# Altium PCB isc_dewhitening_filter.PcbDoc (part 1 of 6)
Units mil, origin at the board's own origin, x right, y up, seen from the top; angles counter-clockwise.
Board outline 8440 x 7000 mil, 6 copper layers (Top Layer, MidLayer1, InternalPlane1, Internal Plane 3, InternalPlane2, Bottom Layer); 550 components, 462 nets, 2189 pads, 795 vias.
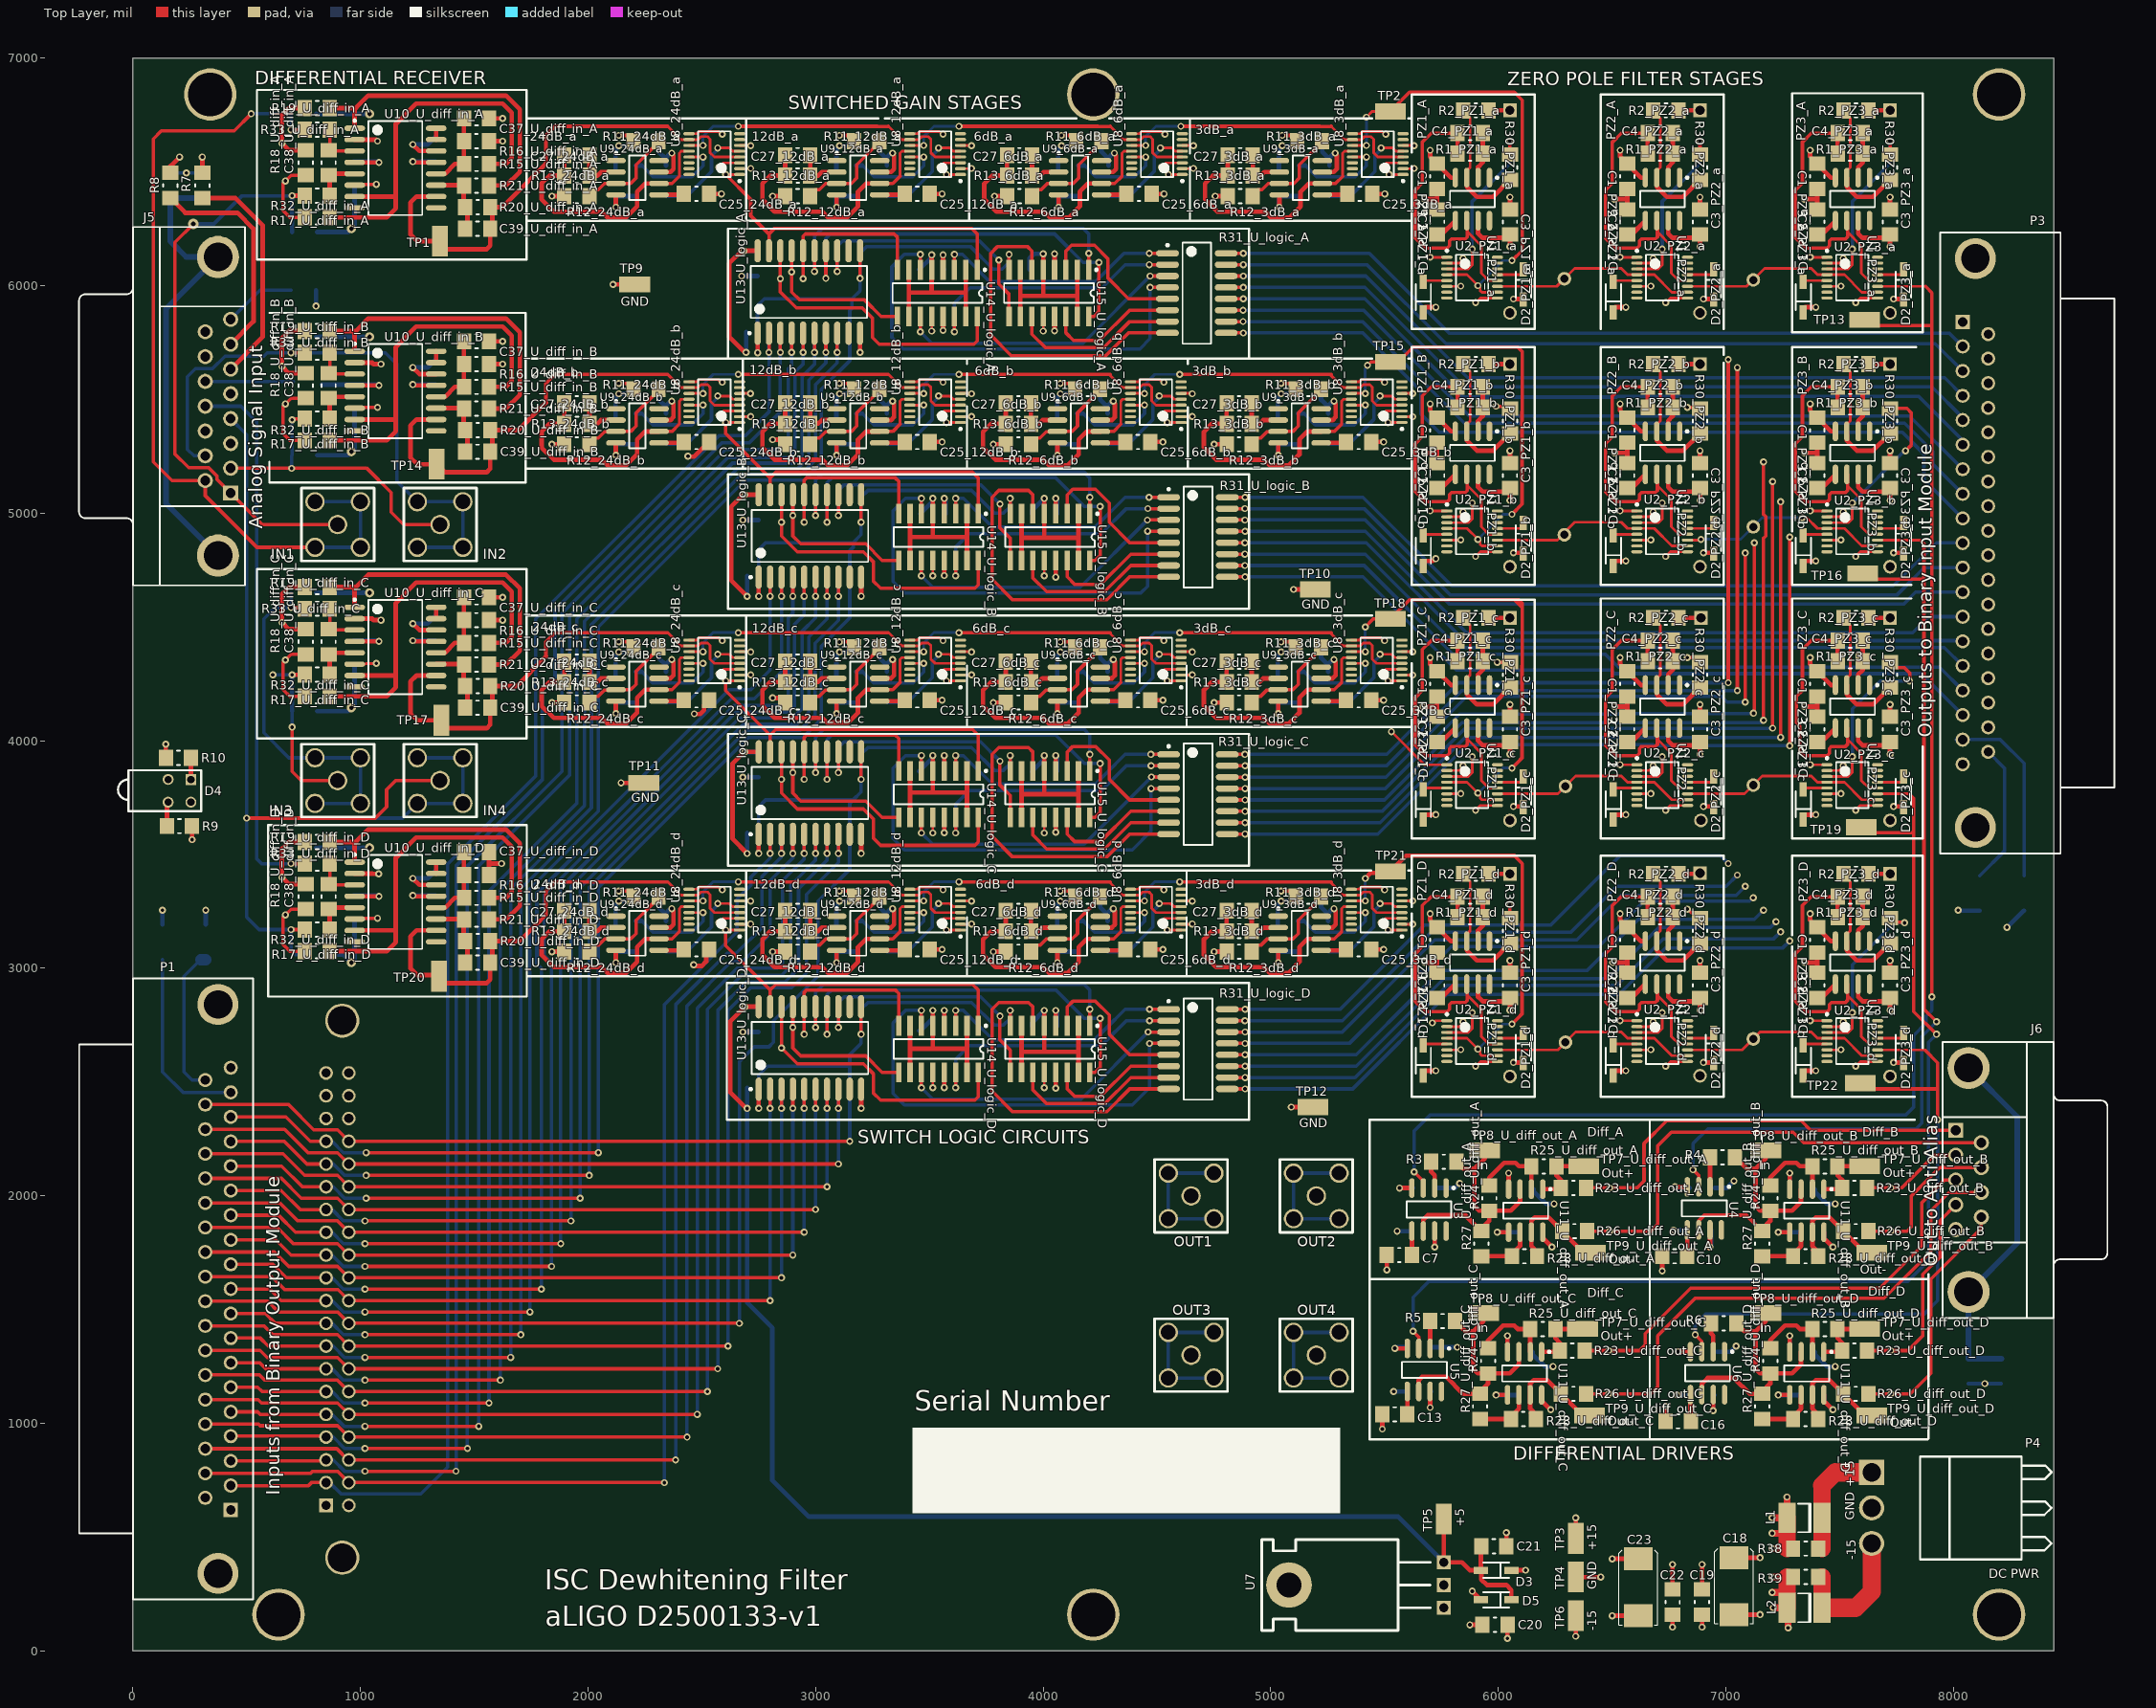
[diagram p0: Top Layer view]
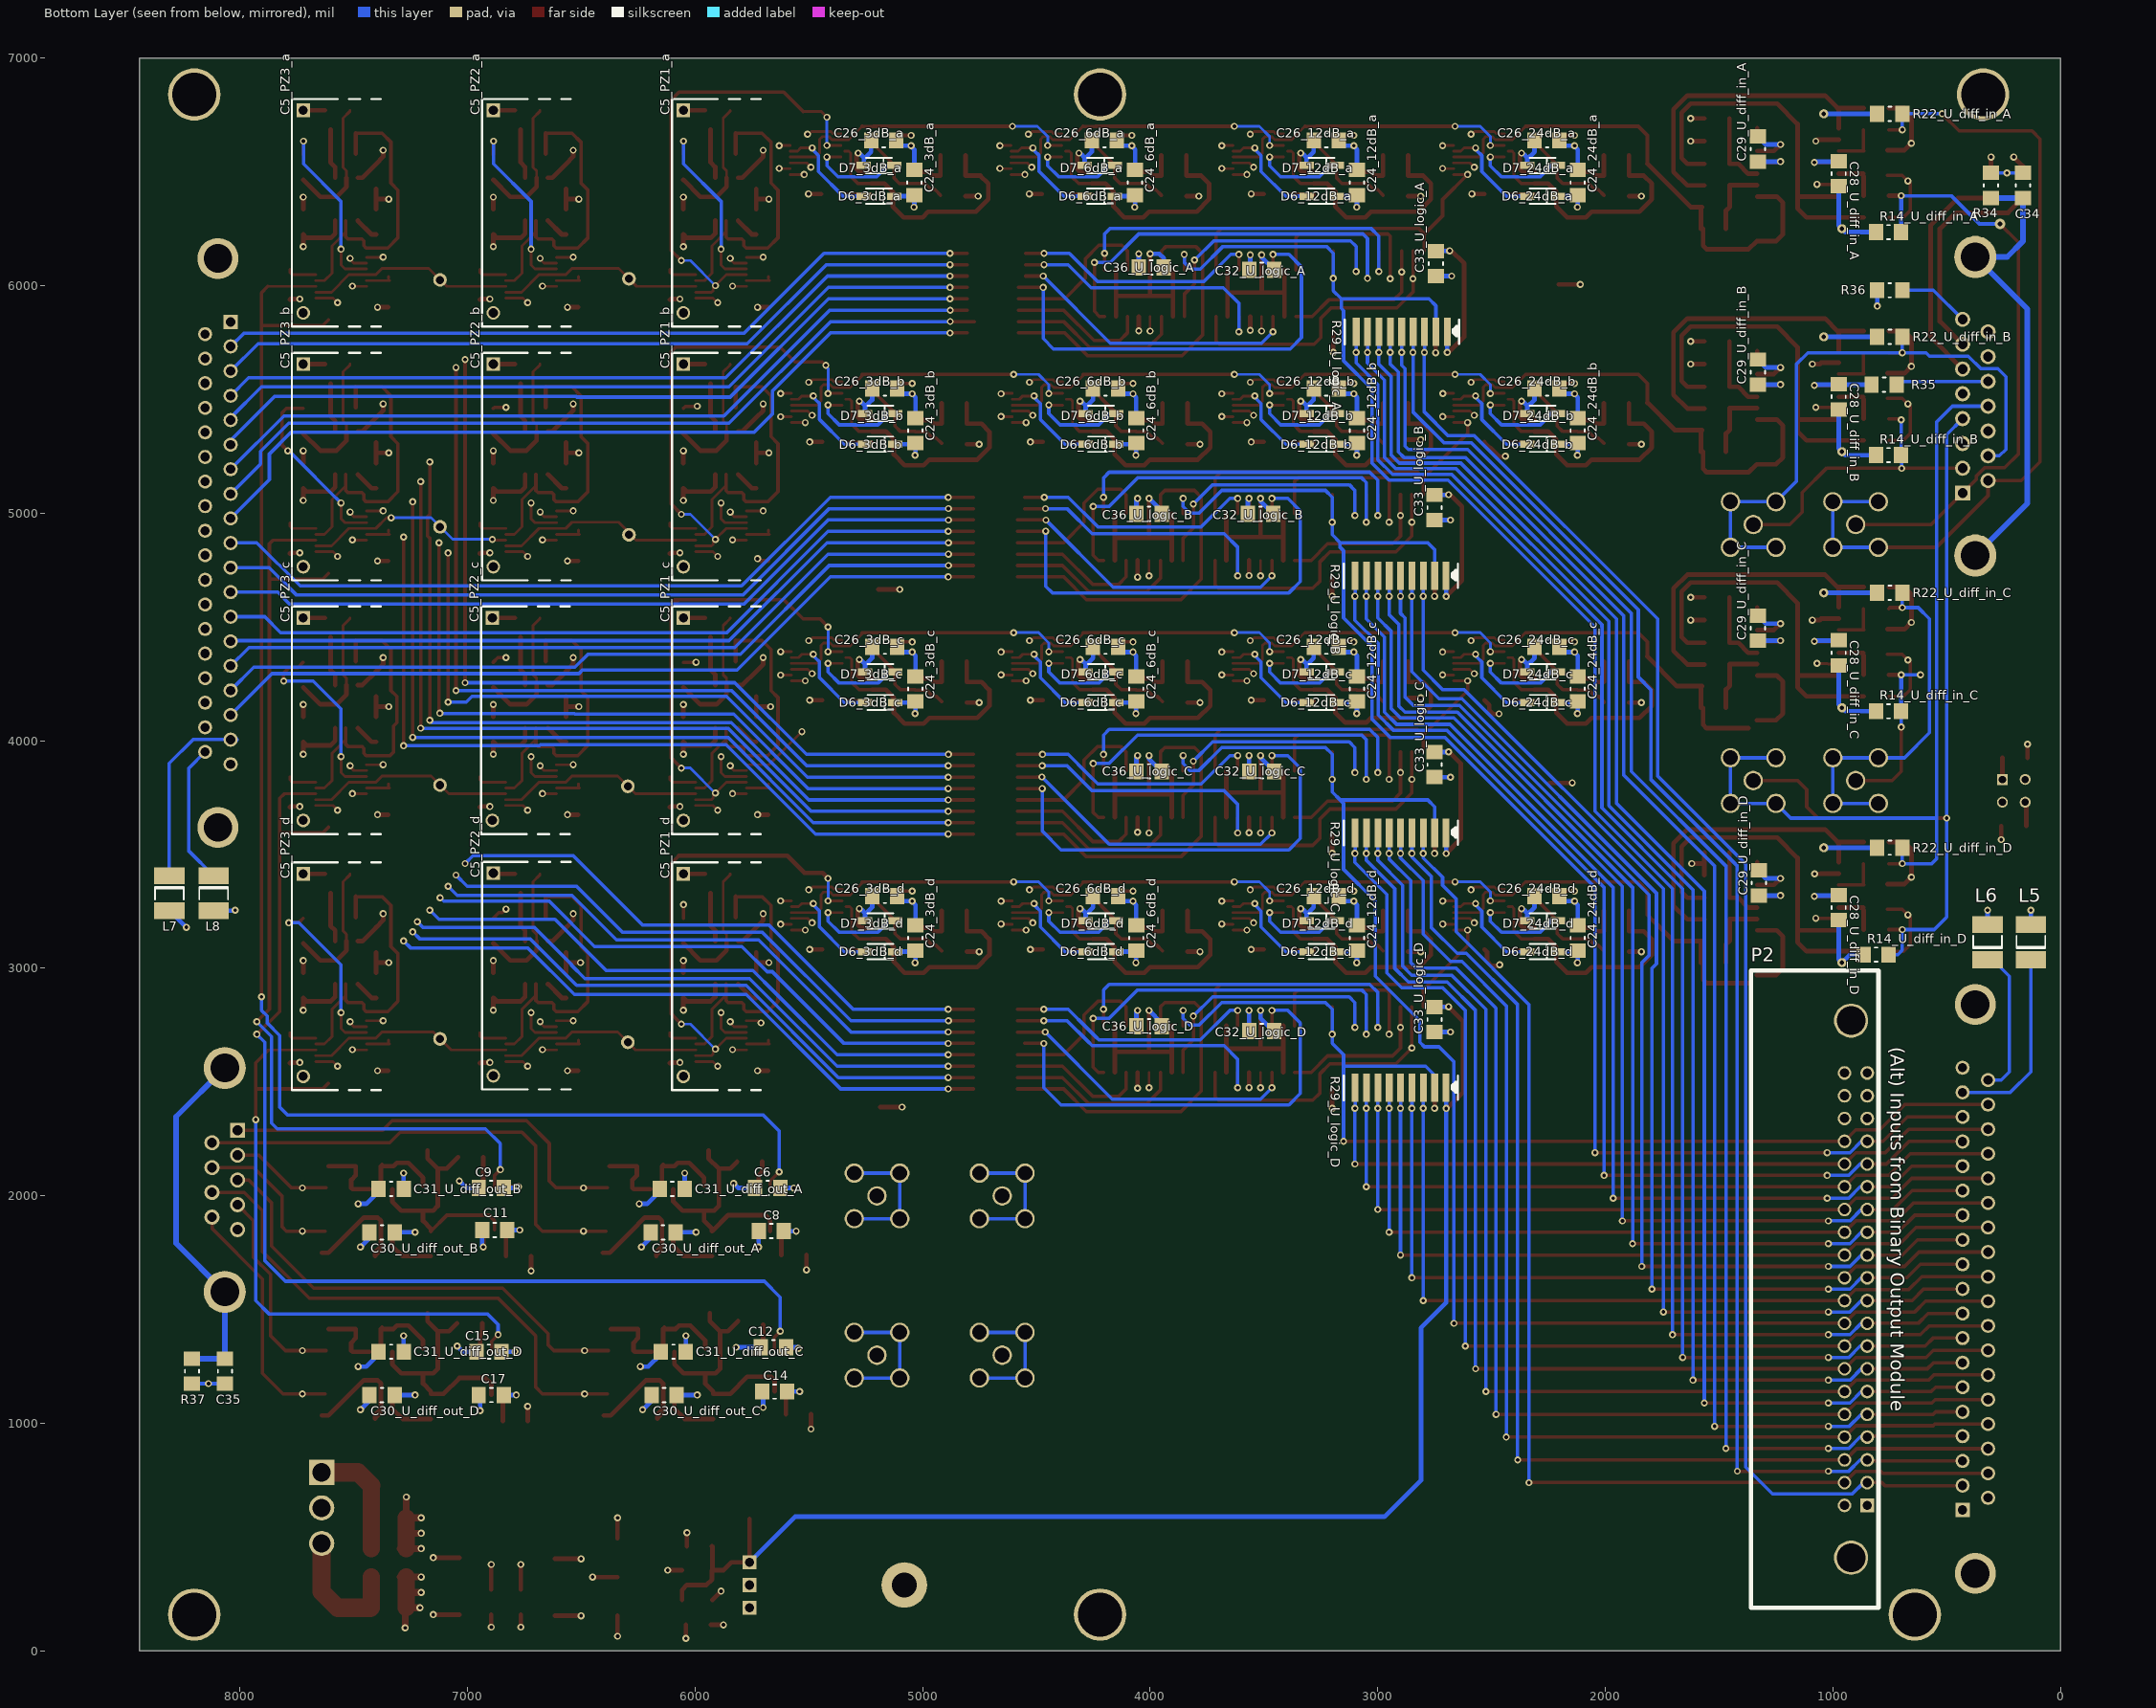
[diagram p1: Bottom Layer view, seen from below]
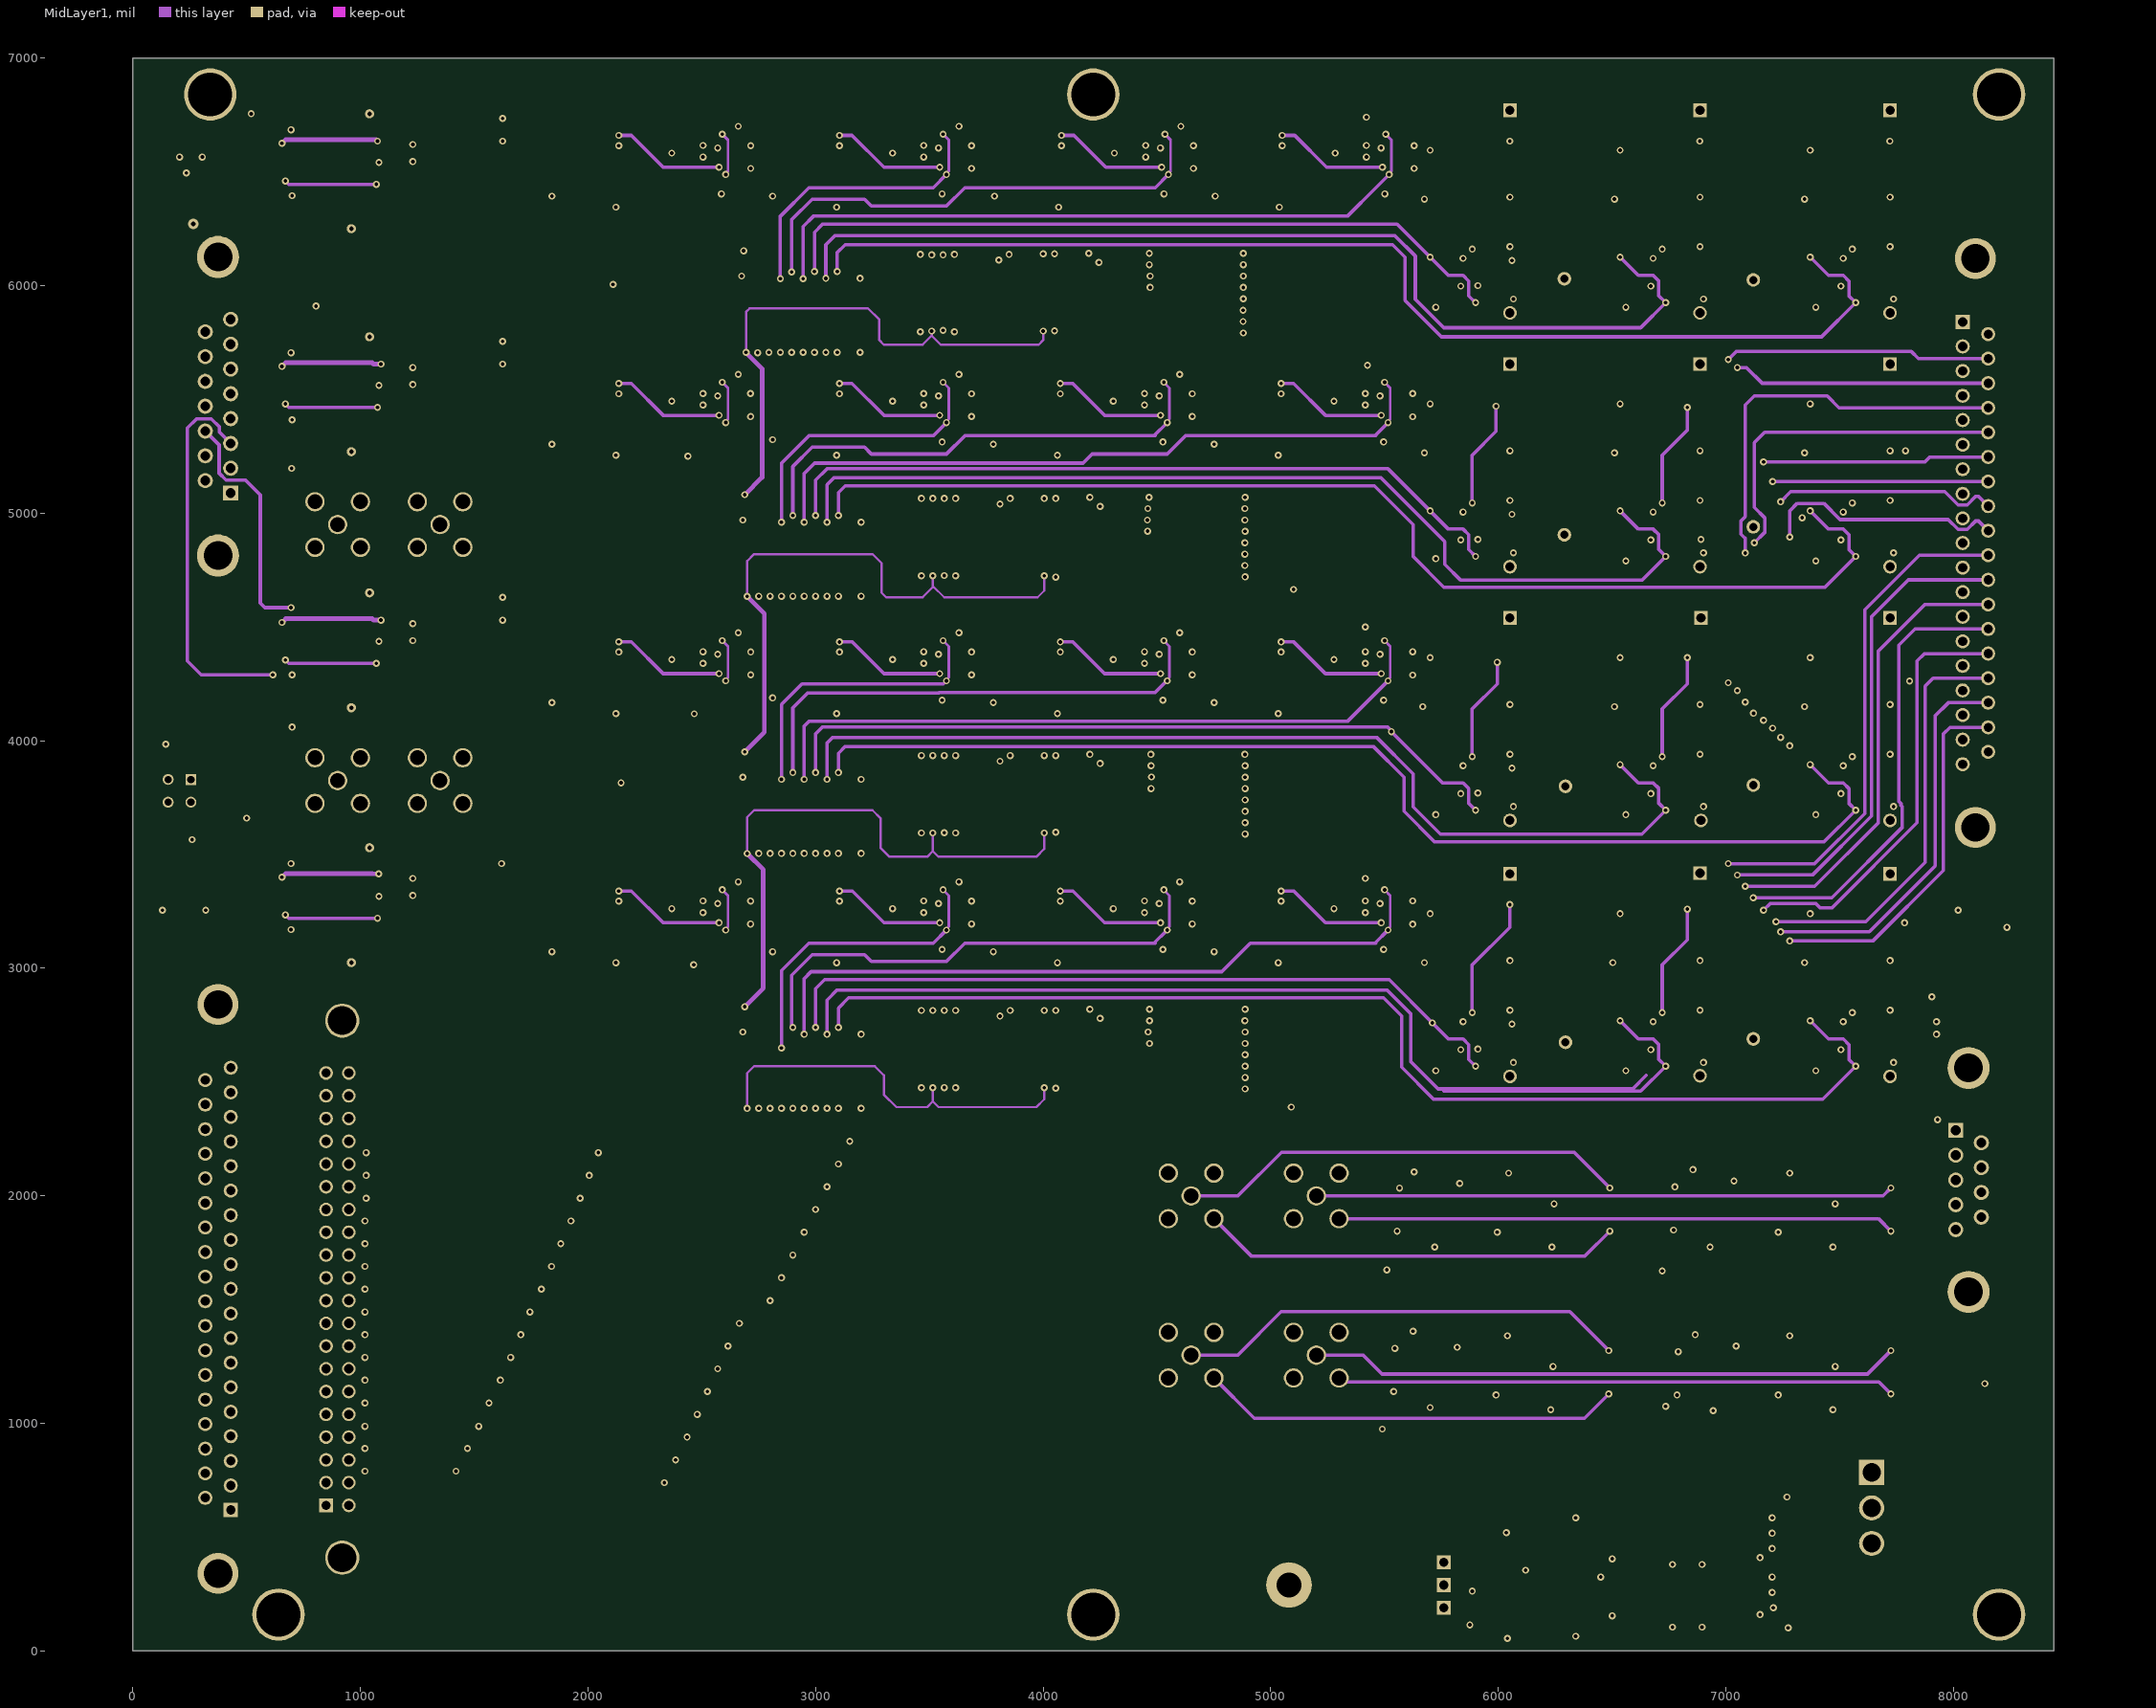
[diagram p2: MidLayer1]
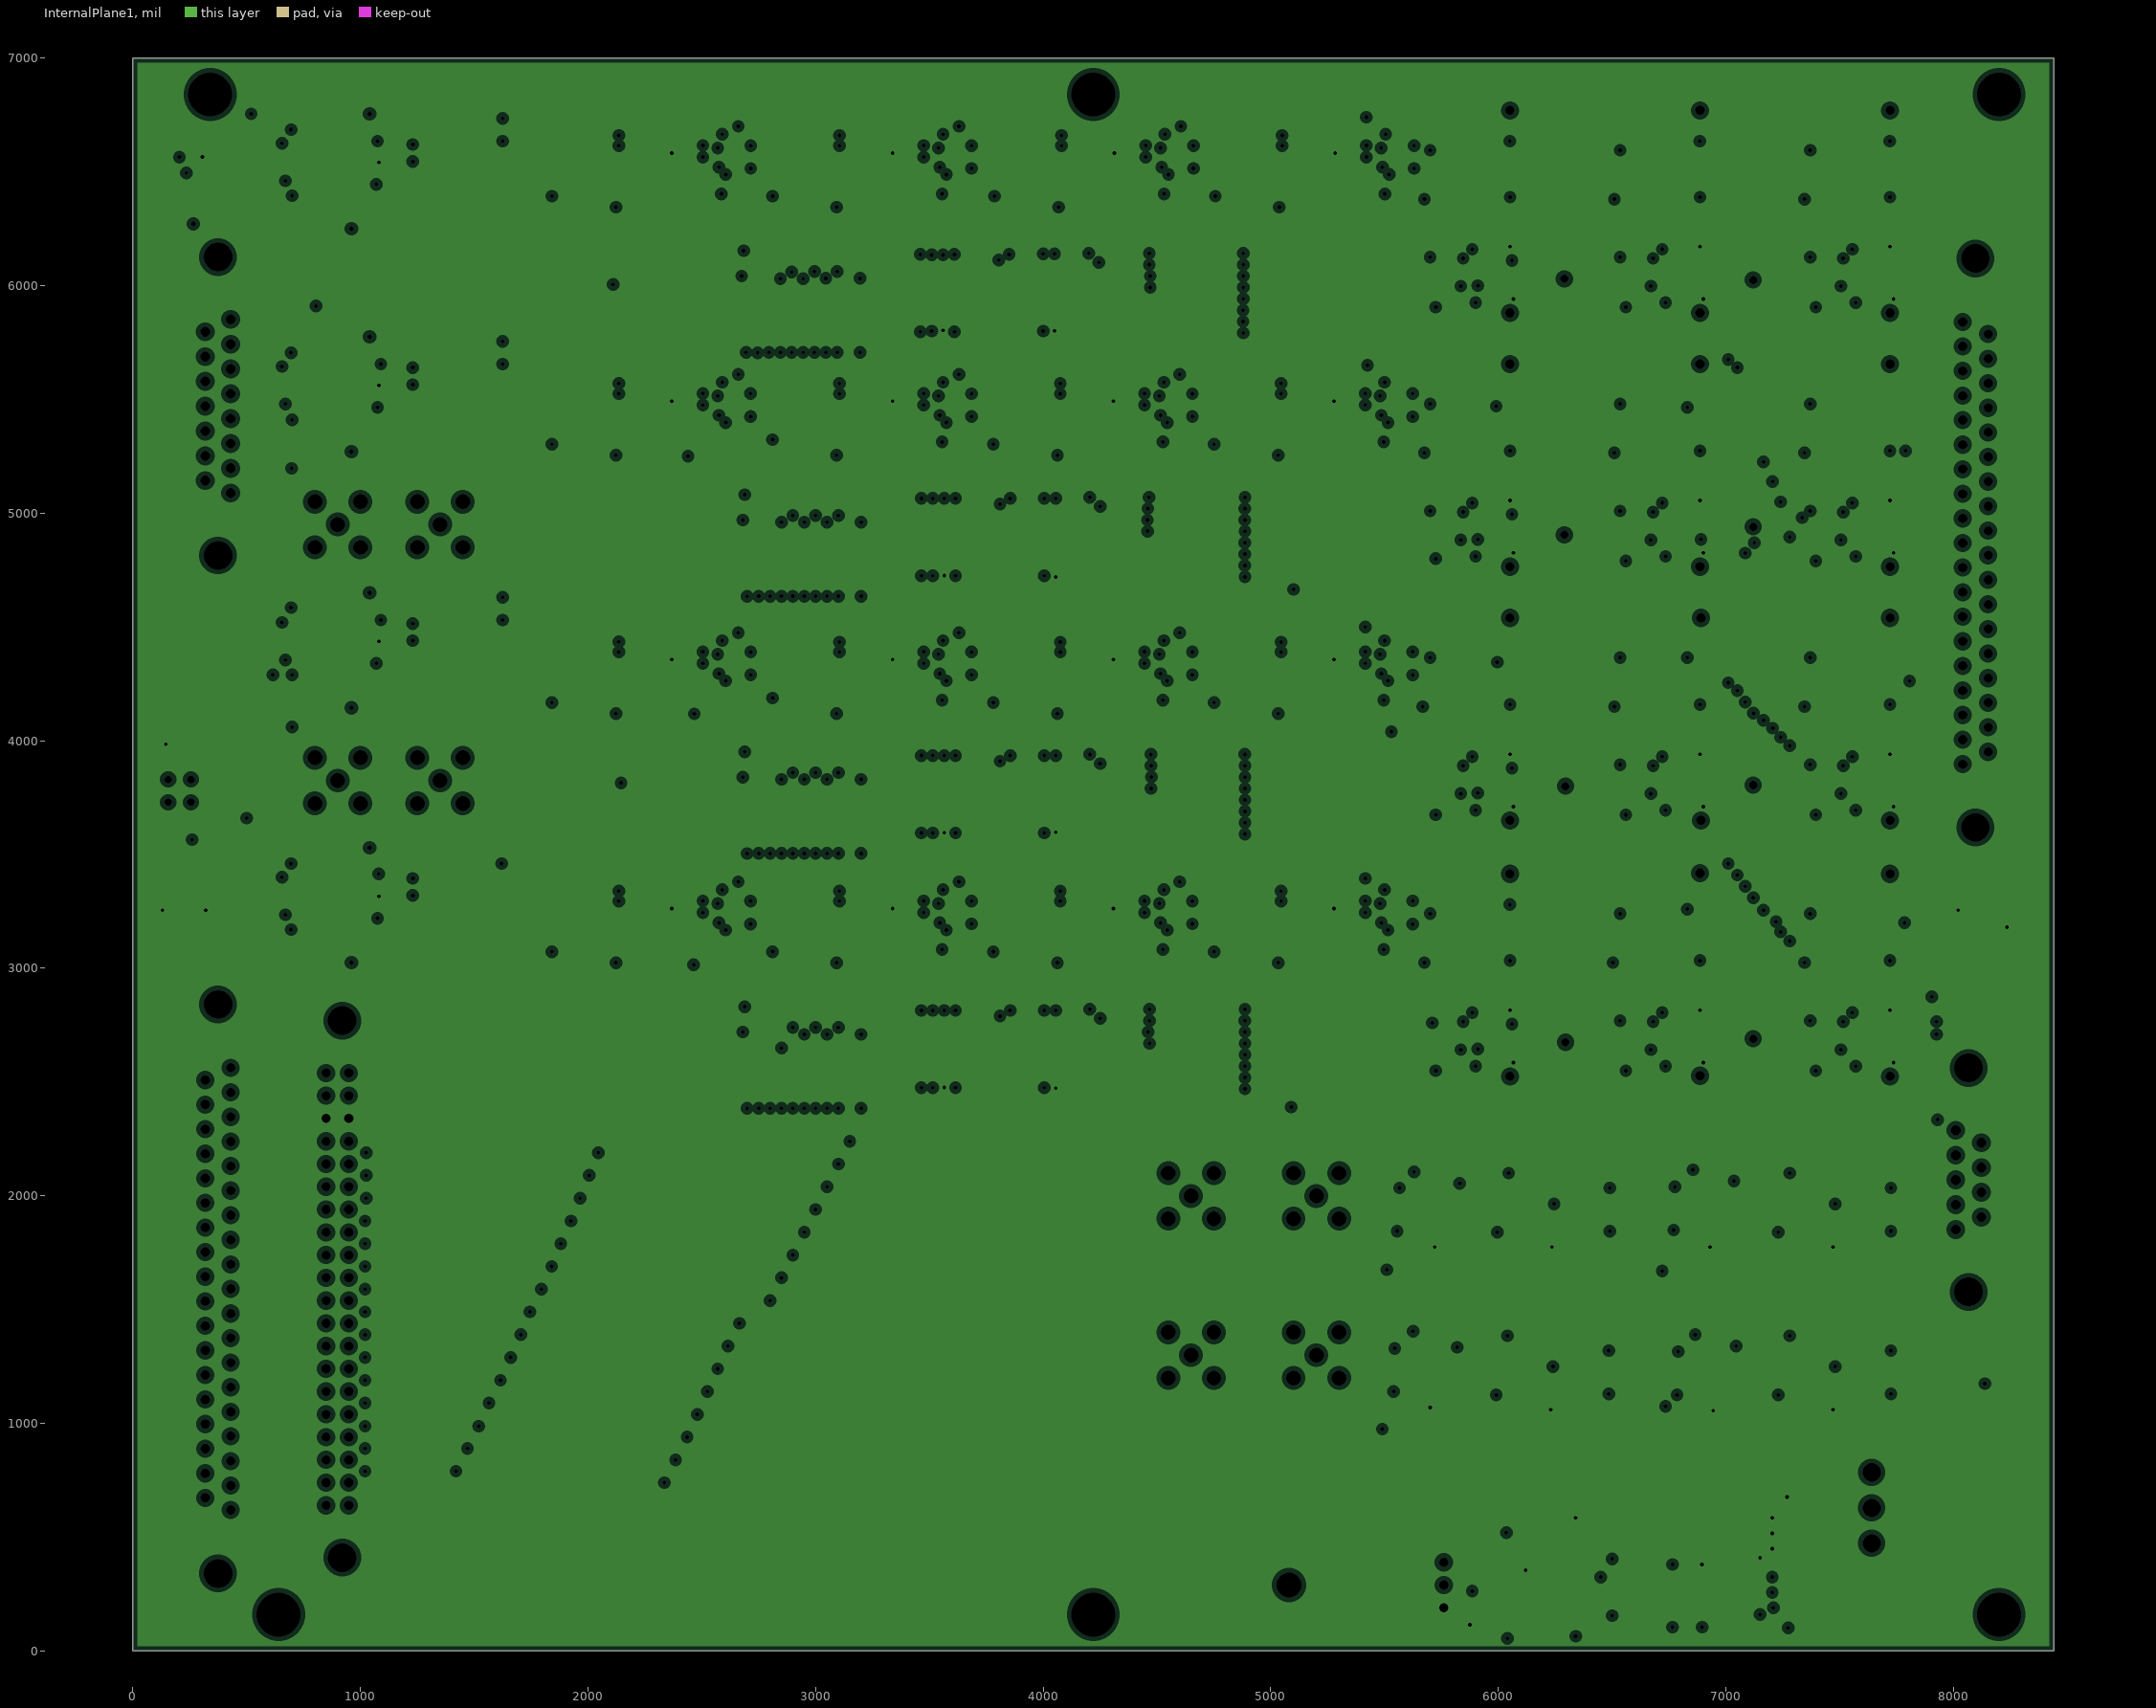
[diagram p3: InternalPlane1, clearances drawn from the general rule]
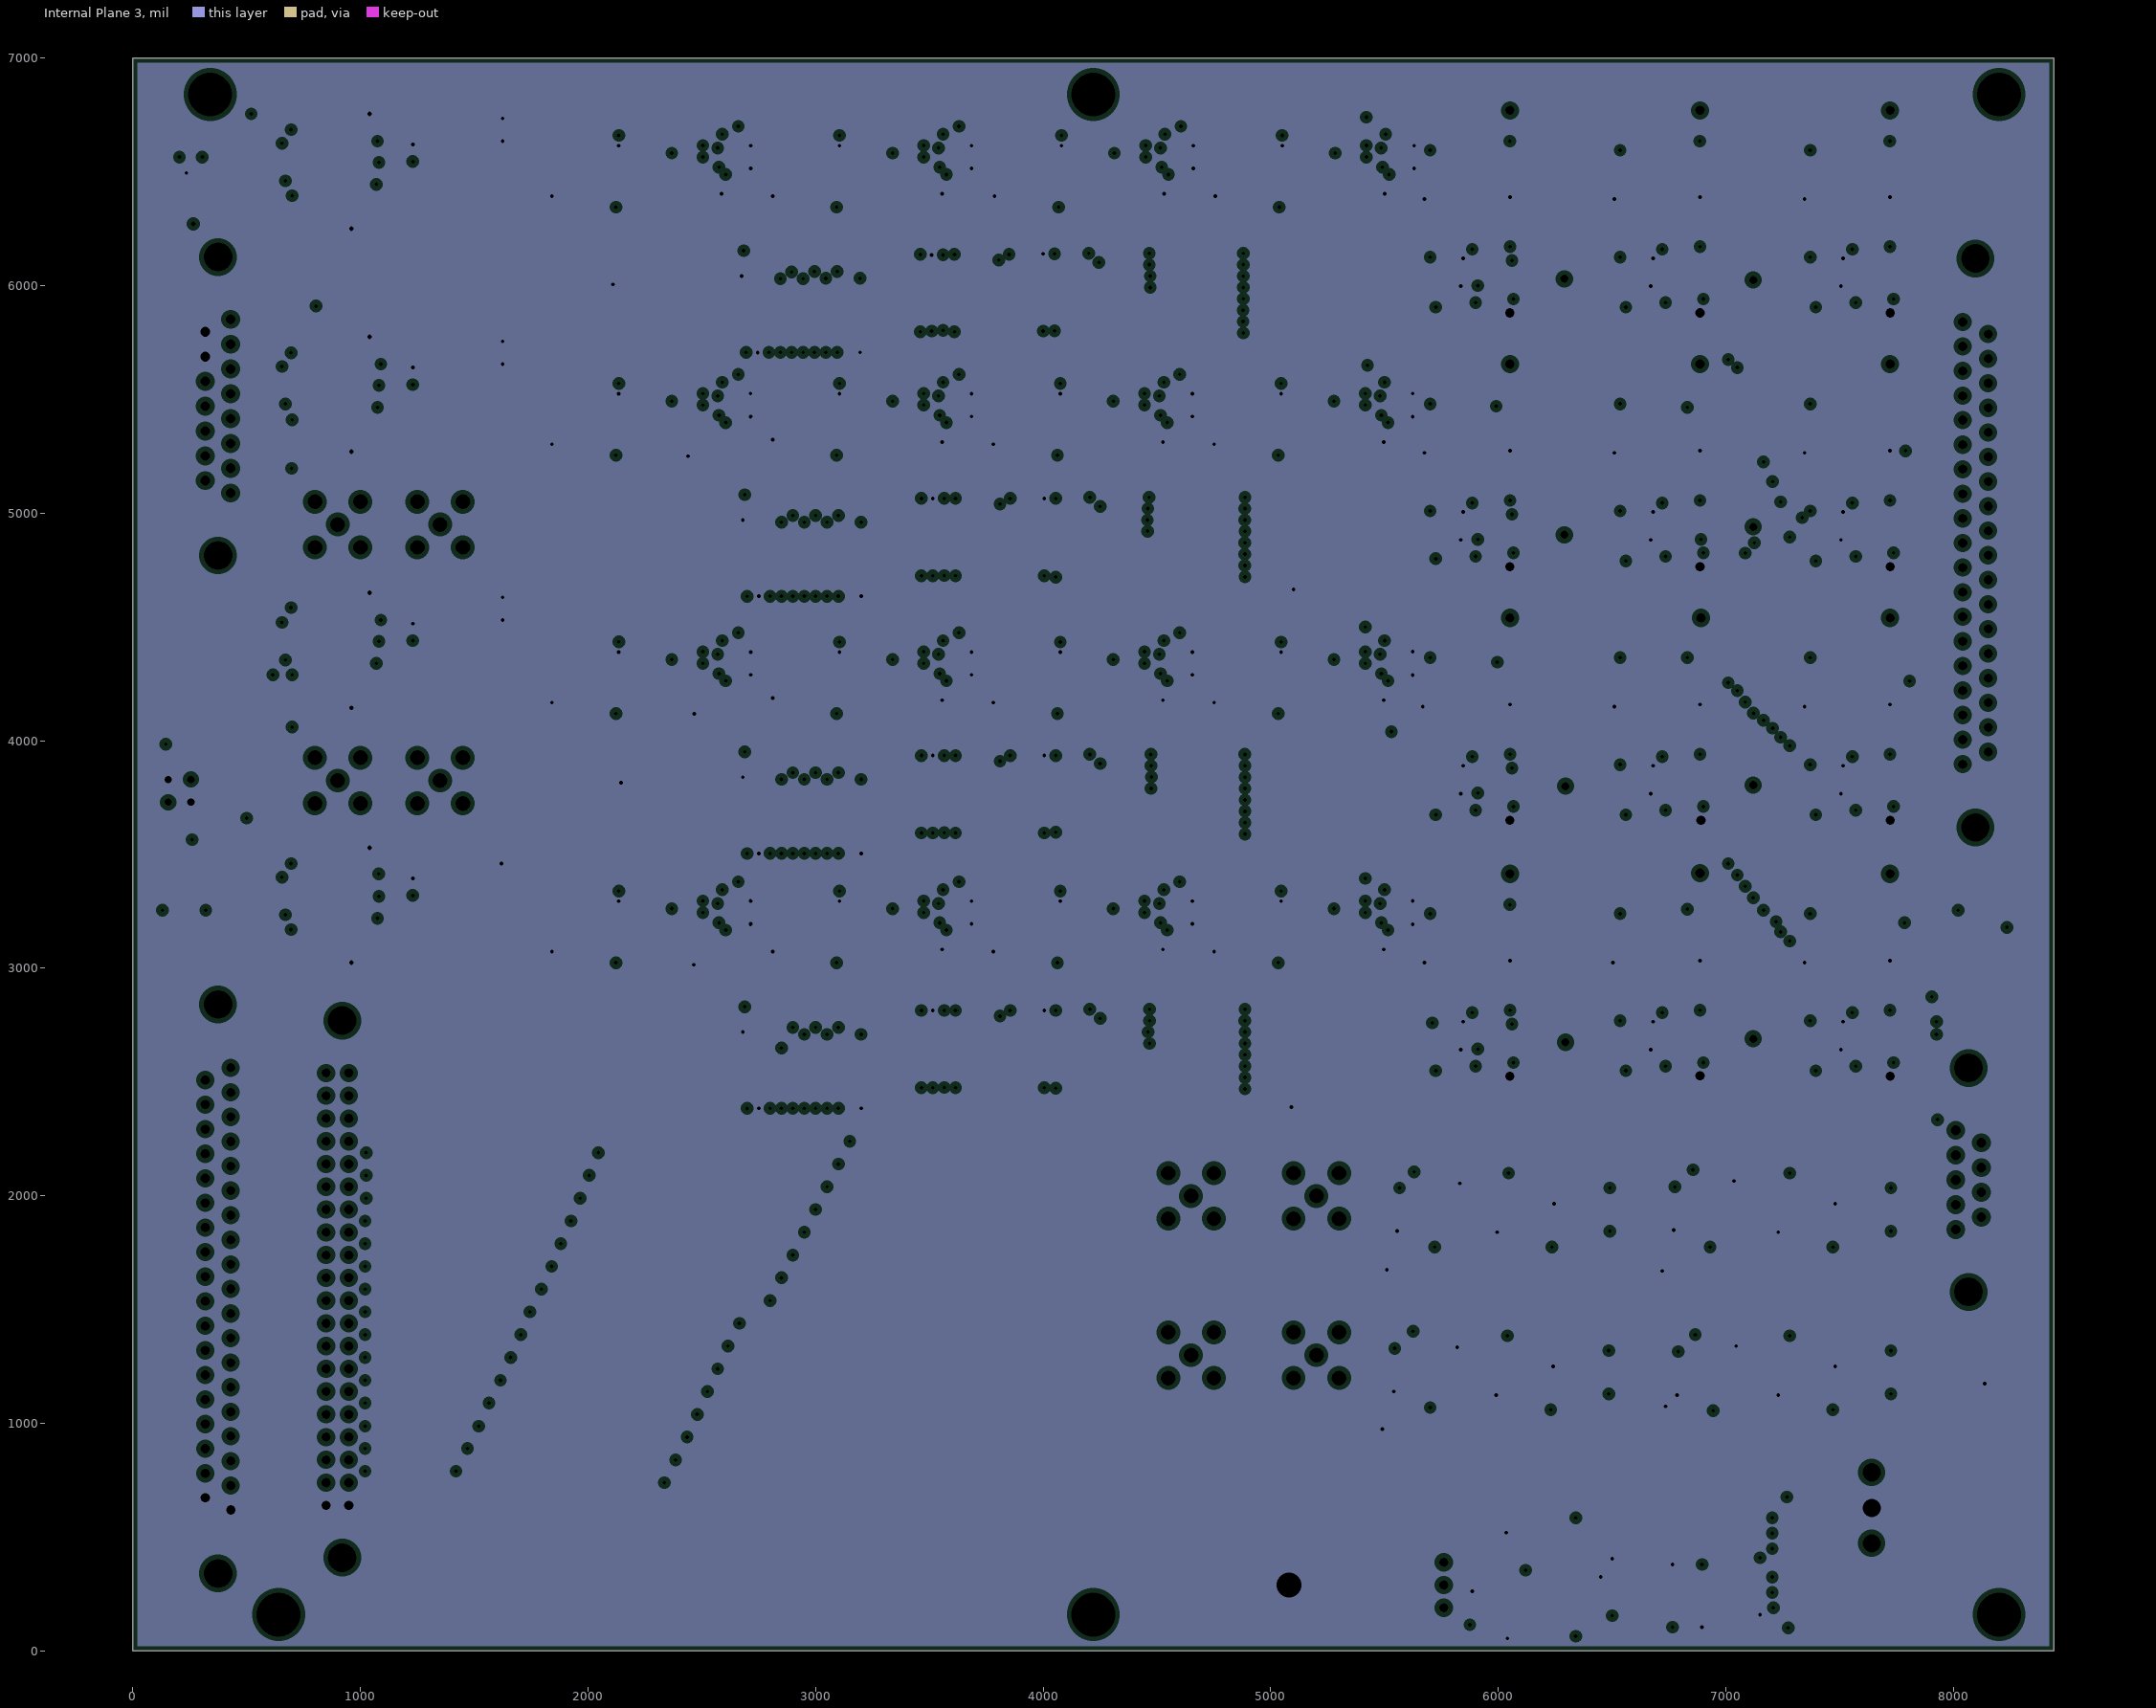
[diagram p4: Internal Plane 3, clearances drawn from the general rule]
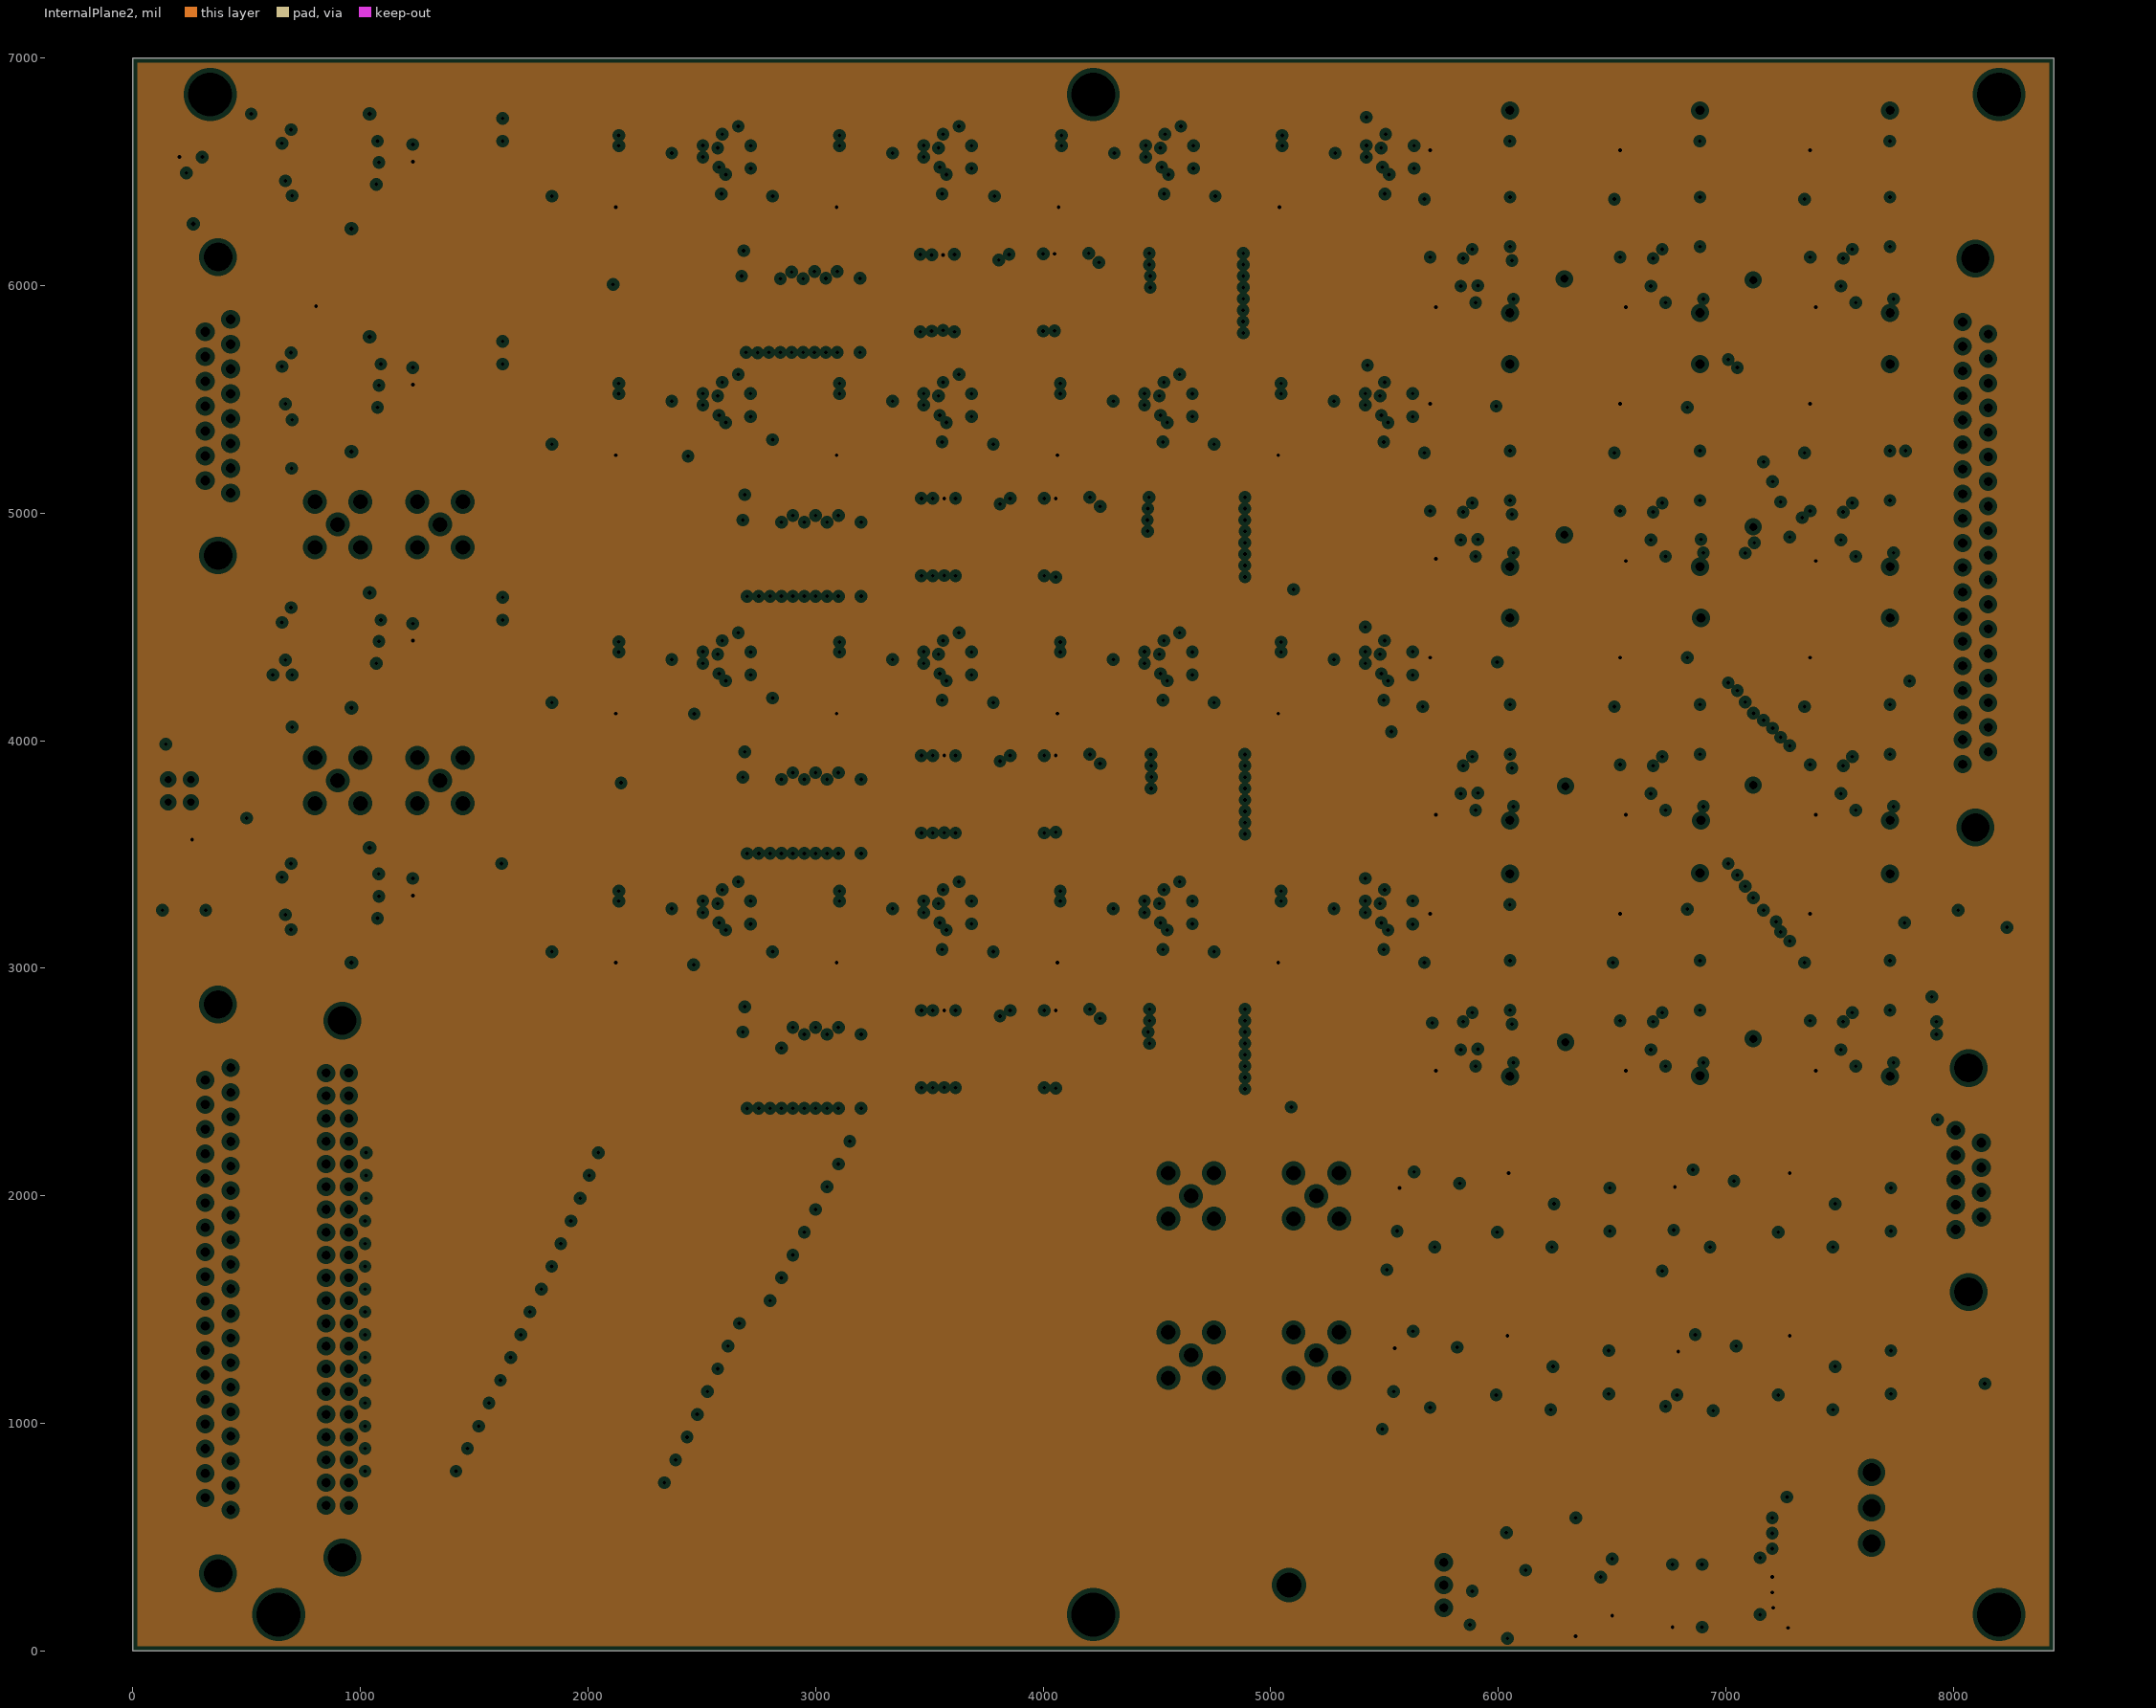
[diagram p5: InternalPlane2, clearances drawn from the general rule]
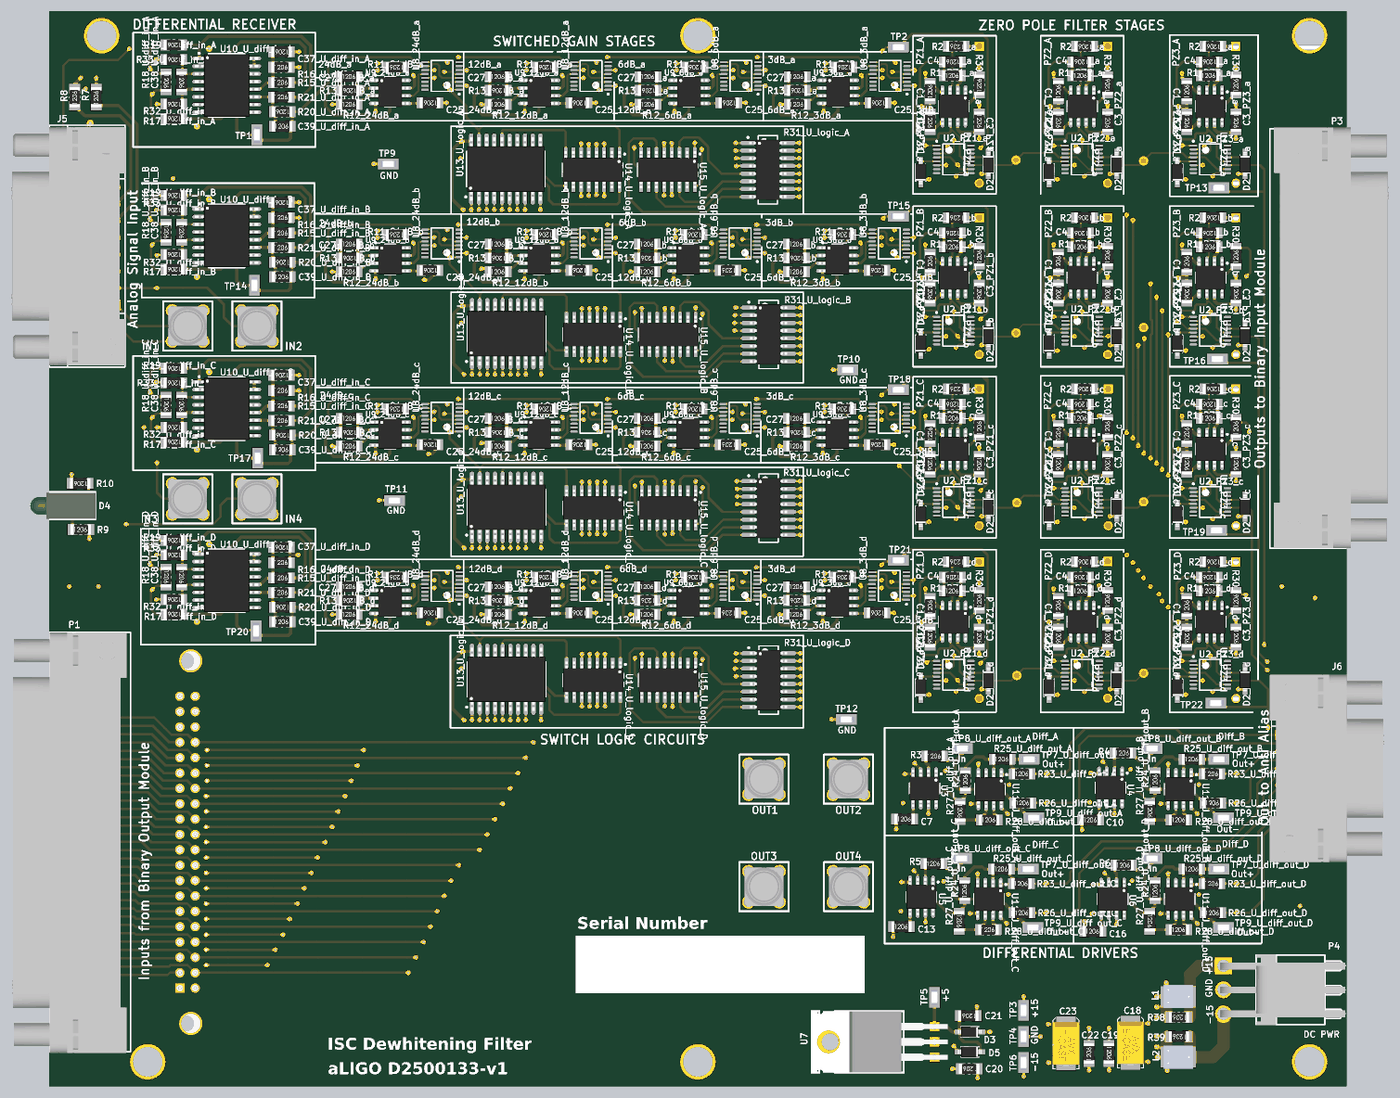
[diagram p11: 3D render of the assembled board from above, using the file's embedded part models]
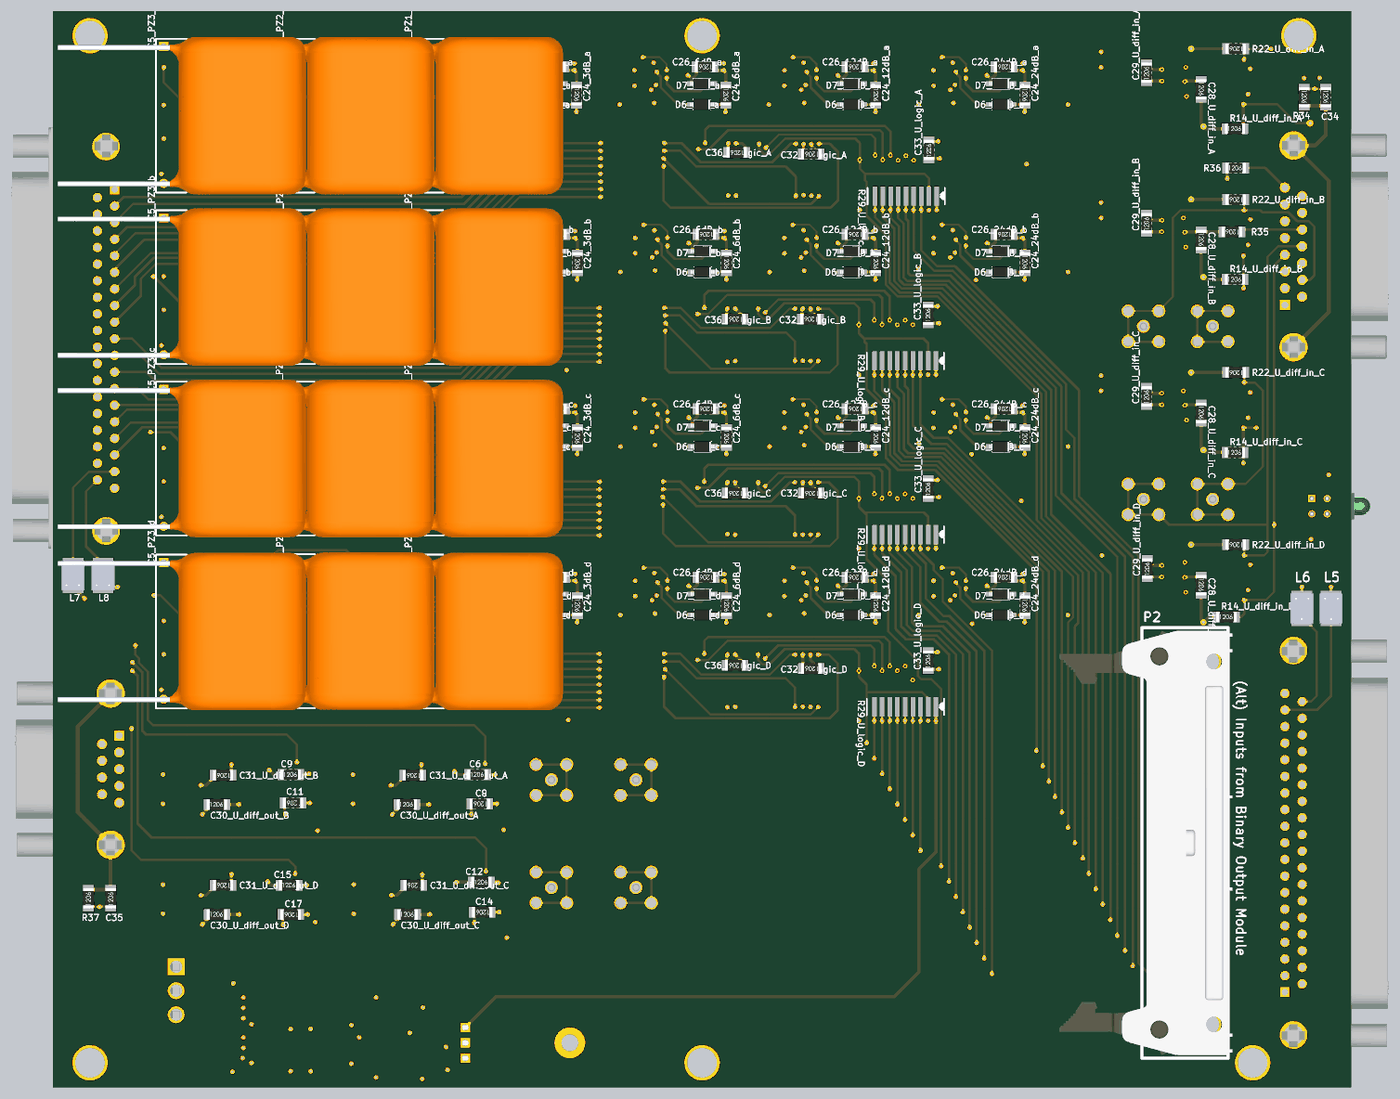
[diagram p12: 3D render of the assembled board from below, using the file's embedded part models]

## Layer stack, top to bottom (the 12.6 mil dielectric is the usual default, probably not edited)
Top Solder: solder mask 0.4, Solder Resist, Dk 3.5
Top Layer: signal copper 1.4
Dielectric1: prepreg 12.6, FR-4, Dk 4.8
MidLayer1: signal copper 1.4
Dielectric2: core 12.6, FR-4, Dk 4.8
InternalPlane1: plane copper 1.4, net +15
Dielectric3: prepreg 12.6, FR-4, Dk 4.8
Internal Plane 3: plane copper 1.4, net GND
Dielectric5: core 12.6, FR-4, Dk 4.8
InternalPlane2: plane copper 1.4, net -15
Dielectric4: prepreg 12.6, FR-4, Dk 4.8
Bottom Layer: signal copper 1.4
Bottom Solder: solder mask 0.4, Solder Resist, Dk 3.5

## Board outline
0,0 8440,0 8440,7000 0,7000

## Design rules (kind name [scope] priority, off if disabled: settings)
Clearance Clearance_1 [(ObjectKind = 'Text') And (TextHeight = AsMils(40)) And (TextWidth = AsMils(7))] p1: gap=10 ignorepadtopadclearanceinfootprint=FALSE
Clearance [All] p2: gap=10 ignorepadtopadclearanceinfootprint=FALSE
DiffPairsRouting DiffPairsRouting_1 [All] p1: maxlimit=10 minlimit=10 mostfreqgap=10 toplayer_minwidth=15 toplayer_maxwidth=15 toplayer_prefwidth=15 midlayer1_minwidth=15 midlayer1_maxwidth=15 midlayer1_prefwidth=15 bottomlayer_minwidth=15 bottomlayer_maxwidth=15 bottomlayer_prefwidth=15 maxuncoupledlength=500
DiffPairsRouting [All] p2: maxlimit=10 minlimit=10 mostfreqgap=10 toplayer_minwidth=15 toplayer_maxwidth=15 toplayer_prefwidth=15 midlayer1_minwidth=15 midlayer1_maxwidth=15 midlayer1_prefwidth=15 bottomlayer_minwidth=15 bottomlayer_maxwidth=15 bottomlayer_prefwidth=15 maxuncoupledlength=500
FabricationTestpoint [(IsPad And (OnTopLayer Or OnBottomLayer))] p1: side=3 testpointundercomponent=TRUE minsize=40 maxsize=100 preferedsize=60 minholesize=0 maxholesize=40 preferedholesize=32 testpointgrid=1 allowsidetop=TRUE allowsidebottom=TRUE usegrid=TRUE gridtolerance=0.01
HoleSize [All] p1: absolutevalues=TRUE maxlimit=200 minlimit=16 maxpercent=80.000 minpercent=20.000
MinimumAnnularRing [All] p1: minimumring=7
PlaneClearance [All] p1: clearance=20
PlaneConnect [All] p1: planeconnectstyle=Relief reliefexpansion=20 reliefentries=4 reliefconductorwidth=10 reliefairgap=10
PolygonConnect [All] p1: connectstyle=Relief reliefconductorwidth=10 reliefentries=4 polygonreliefangle="90 Angle" airgapwidth=10
RoomDefinition 3dB_a [InComponentClass('3dB_a')] p1: confinementstyle=ConfineIn formatcopy=FALSE lockcomponents=FALSE outline 4650,6285 5615,6285 5615,6735 4650,6735
RoomDefinition 3dB_b [InComponentClass('3dB_b')] p2: confinementstyle=ConfineIn formatcopy=TRUE lockcomponents=FALSE outline 4650,5195 5615,5195 5615,5645 4650,5645
RoomDefinition 3dB_c [InComponentClass('3dB_c')] p3: confinementstyle=ConfineIn formatcopy=TRUE lockcomponents=FALSE outline 4650,4060 5615,4060 5615,4510 4650,4510
RoomDefinition 3dB_d [InComponentClass('3dB_d')] p4: confinementstyle=ConfineIn formatcopy=TRUE lockcomponents=FALSE outline 4650,2965 5615,2965 5615,3415 4650,3415
RoomDefinition 6dB_a [InComponentClass('6dB_a')] p5: confinementstyle=ConfineIn formatcopy=FALSE lockcomponents=TRUE outline 3680,6285 4645,6285 4645,6735 3680,6735
RoomDefinition 6dB_b [InComponentClass('6dB_b')] p6: confinementstyle=ConfineIn formatcopy=TRUE lockcomponents=FALSE outline 3680,5195 4645,5195 4645,5645 3680,5645
RoomDefinition 6dB_c [InComponentClass('6dB_c')] p7: confinementstyle=ConfineIn formatcopy=TRUE lockcomponents=FALSE outline 3680,4060 4645,4060 4645,4510 3680,4510
RoomDefinition 6dB_d [InComponentClass('6dB_d')] p8: confinementstyle=ConfineIn formatcopy=TRUE lockcomponents=FALSE outline 3680,2965 4645,2965 4645,3415 3680,3415
RoomDefinition 12dB_a [InComponentClass('12dB_a')] p9: confinementstyle=ConfineIn formatcopy=FALSE lockcomponents=FALSE outline 2710,6285 3675,6285 3675,6735 2710,6735
RoomDefinition 12dB_b [InComponentClass('12dB_b')] p10: confinementstyle=ConfineIn formatcopy=TRUE lockcomponents=FALSE outline 2710,5195 3675,5195 3675,5645 2710,5645
RoomDefinition 12dB_c [InComponentClass('12dB_c')] p11: confinementstyle=ConfineIn formatcopy=TRUE lockcomponents=FALSE outline 2710,4060 3675,4060 3675,4510 2710,4510
RoomDefinition 12dB_d [InComponentClass('12dB_d')] p12: confinementstyle=ConfineIn formatcopy=TRUE lockcomponents=FALSE outline 2710,2965 3675,2965 3675,3415 2710,3415
RoomDefinition 24dB_a [InComponentClass('24dB_a')] p13: confinementstyle=ConfineIn formatcopy=FALSE lockcomponents=FALSE outline 1740,6285 2705,6285 2705,6735 1740,6735
RoomDefinition 24dB_b [InComponentClass('24dB_b')] p14: confinementstyle=ConfineIn formatcopy=FALSE lockcomponents=FALSE outline 1740,5195 2705,5195 2705,5645 1740,5645
RoomDefinition 24dB_c [InComponentClass('24dB_c')] p15: confinementstyle=ConfineIn formatcopy=FALSE lockcomponents=FALSE outline 1740,4060 2705,4060 2705,4510 1740,4510
RoomDefinition 24dB_d [InComponentClass('24dB_d')] p16: confinementstyle=ConfineIn formatcopy=FALSE lockcomponents=FALSE outline 1740,2965 2705,2965 2705,3415 1740,3415
RoomDefinition U_logic_A [InComponentClass('U_logic_A')] p17: confinementstyle=ConfineIn formatcopy=TRUE lockcomponents=FALSE outline 4905,6285 2635,6285 2635,5670 4905,5670
RoomDefinition U_logic_B [InComponentClass('U_logic_B')] p18: confinementstyle=ConfineIn formatcopy=TRUE lockcomponents=FALSE outline 4900,5215 2640,5215 2640,4585 4900,4585
RoomDefinition U_logic_C [InComponentClass('U_logic_C')] p19: confinementstyle=ConfineIn formatcopy=TRUE lockcomponents=FALSE outline 4910,4090 2640,4090 2640,3450 4910,3450
RoomDefinition U_logic_D [InComponentClass('U_logic_D')] p20: confinementstyle=ConfineIn formatcopy=TRUE lockcomponents=FALSE outline 4900,2955 2640,2955 2640,2340 4900,2340
RoomDefinition U_diff_out_A [InComponentClass('U_diff_out_A')] p21: confinementstyle=ConfineIn formatcopy=TRUE lockcomponents=FALSE outline 5855,1690 6590,1690 6590,2245 5855,2245
RoomDefinition U_diff_out_B [InComponentClass('U_diff_out_B')] p22: confinementstyle=ConfineIn formatcopy=TRUE lockcomponents=FALSE outline 7090,1690 7825,1690 7825,2250 7090,2250
RoomDefinition U_diff_out_C [InComponentClass('U_diff_out_C')] p23: confinementstyle=ConfineIn formatcopy=TRUE lockcomponents=FALSE outline 5850,975 6585,975 6585,1535 5850,1535
RoomDefinition U_diff_out_D [InComponentClass('U_diff_out_D')] p24: confinementstyle=ConfineIn formatcopy=TRUE lockcomponents=FALSE outline 7090,975 7825,975 7825,1530 7090,1530
RoomDefinition U_diff_in_A [InComponentClass('U_diff_in_A')] p25: confinementstyle=ConfineIn formatcopy=TRUE lockcomponents=FALSE outline 600,6115 1725,6115 1725,6860 600,6860
RoomDefinition U_diff_in_B [InComponentClass('U_diff_in_B')] p26: confinementstyle=ConfineIn formatcopy=TRUE lockcomponents=FALSE outline 600,5135 1725,5135 1725,5880 600,5880
RoomDefinition U_diff_in_C [InComponentClass('U_diff_in_C')] p27: confinementstyle=ConfineIn formatcopy=TRUE lockcomponents=FALSE outline 600,4010 1725,4010 1725,4755 600,4755
RoomDefinition U_diff_in_D [InComponentClass('U_diff_in_D')] p28: confinementstyle=ConfineIn formatcopy=TRUE lockcomponents=FALSE outline 600,2890 1725,2890 1725,3635 600,3635
RoomDefinition PZ1_a [InComponentClass('PZ1_a') and not HasFootprint('ECQ-E1106KF_Side')] p29: confinementstyle=ConfineIn formatcopy=TRUE lockcomponents=FALSE outline 5620,5800 6150,5800 6150,6840 5620,6840
RoomDefinition PZ1_b [InComponentClass('PZ1_b') and not HasFootprint('ECQ-E1106KF_Side')] p30: confinementstyle=ConfineIn formatcopy=TRUE lockcomponents=FALSE outline 5620,4685 6150,4685 6150,5725 5620,5725
RoomDefinition PZ1_c [InComponentClass('PZ1_c') and not HasFootprint('ECQ-E1106KF_Side')] p31: confinementstyle=ConfineIn formatcopy=TRUE lockcomponents=FALSE outline 5620,3570 6150,3570 6150,4610 5620,4610
RoomDefinition PZ1_d [InComponentClass('PZ1_d') and not HasFootprint('ECQ-E1106KF_Side')] p32: confinementstyle=ConfineIn formatcopy=TRUE lockcomponents=FALSE outline 5620,2445 6150,2445 6150,3485 5620,3485
RoomDefinition PZ2_a [InComponentClass('PZ2_a') and not HasFootprint('ECQ-E1106KF_Side')] p33: confinementstyle=ConfineIn formatcopy=TRUE lockcomponents=FALSE outline 6455,5800 6985,5800 6985,6840 6455,6840
RoomDefinition PZ2_b [InComponentClass('PZ2_b') and not HasFootprint('ECQ-E1106KF_Side')] p34: confinementstyle=ConfineIn formatcopy=TRUE lockcomponents=FALSE outline 6455,4685 6985,4685 6985,5725 6455,5725
RoomDefinition PZ2_c [InComponentClass('PZ2_c') and not HasFootprint('ECQ-E1106KF_Side')] p35: confinementstyle=ConfineIn formatcopy=TRUE lockcomponents=FALSE outline 6455,3570 6985,3570 6985,4610 6455,4610
RoomDefinition PZ2_d [InComponentClass('PZ2_d') and not HasFootprint('ECQ-E1106KF_Side')] p36: confinementstyle=ConfineIn formatcopy=TRUE lockcomponents=FALSE outline 6455,2445 6985,2445 6985,3485 6455,3485
RoomDefinition PZ3_a [InComponentClass('PZ3_a') and not HasFootprint('ECQ-E1106KF_Side')] p37: confinementstyle=ConfineIn formatcopy=TRUE lockcomponents=FALSE outline 7290,5800 7820,5800 7820,6840 7290,6840
RoomDefinition PZ3_b [InComponentClass('PZ3_b') and not HasFootprint('ECQ-E1106KF_Side')] p38: confinementstyle=ConfineIn formatcopy=TRUE lockcomponents=FALSE outline 7290,4685 7820,4685 7820,5725 7290,5725
RoomDefinition PZ3_c [InComponentClass('PZ3_c') and not HasFootprint('ECQ-E1106KF_Side')] p39: confinementstyle=ConfineIn formatcopy=TRUE lockcomponents=FALSE outline 7290,3570 7820,3570 7820,4610 7290,4610
RoomDefinition PZ3_d [InComponentClass('PZ3_d') and not HasFootprint('ECQ-E1106KF_Side')] p40: confinementstyle=ConfineIn formatcopy=TRUE lockcomponents=FALSE outline 7290,2445 7820,2445 7820,3485 7290,3485
RoutingVias [All] p1: holewidth=16 width=31 viastyle="Through Hole" minholewidth=16 minwidth=31 maxholewidth=16 maxwidth=31
SilkToSolderMaskClearance SilkscreenOverComponentPads [IsPad] p1: minsilkscreentomaskgap=10 clearancetoexposedcopper=TRUE
SolderMaskExpansion [All] p1: expansion=4 istentingtop=FALSE
SupplyNets "Schematic Supply Nets_3" [InNet('GND')] p1: voltage=0.000
SupplyNets "Schematic Supply Nets_2" [InNet('-15')] p2: voltage=0.000
SupplyNets "Schematic Supply Nets_1" [InNet('+15')] p3: voltage=0.000
SupplyNets "Schematic Supply Nets" [InNet('VCC')] p4: voltage=0.000
Width [All] p1: maxlimit=100 minlimit=9 preferedwidth=15
24 further rules are at their usual default settings.

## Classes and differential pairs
channel class VGA2: 3dB_a 3dB_b 3dB_c 3dB_d 6dB_a 6dB_b 6dB_c 6dB_d 12dB_a 12dB_b 12dB_c 12dB_d 24dB_a 24dB_b 24dB_c 24dB_d
channel class filter2: PZ1_a PZ1_b PZ1_c PZ1_d PZ2_a PZ2_b PZ2_c PZ2_d PZ3_a PZ3_b PZ3_c PZ3_d
channel class diff_in2: U_diff_in_A U_diff_in_B U_diff_in_C U_diff_in_D
component class U_logic_D: C32_U_logic_D C33_U_logic_D C34_U_logic_D C35_U_logic_D C36_U_logic_D R29_U_logic_D R31_U_logic_D U13_U_logic_D U14_U_logic_D U15_U_logic_D
component class U_logic_C: C32_U_logic_C C33_U_logic_C C34_U_logic_C C35_U_logic_C C36_U_logic_C R29_U_logic_C R31_U_logic_C U13_U_logic_C U14_U_logic_C U15_U_logic_C
component class U_logic_B: C32_U_logic_B C33_U_logic_B C34_U_logic_B C35_U_logic_B C36_U_logic_B R29_U_logic_B R31_U_logic_B U13_U_logic_B U14_U_logic_B U15_U_logic_B
component class U_logic_A: C32_U_logic_A C33_U_logic_A C34_U_logic_A C35_U_logic_A C36_U_logic_A R29_U_logic_A R31_U_logic_A U13_U_logic_A U14_U_logic_A U15_U_logic_A
component class PZ3_b: C1_PZ3_b C1_U_83 C2_PZ3_b C2_U_83 C3_PZ3_b C3_U_83 C4_PZ3_b C5_PZ3_b C5_U_83 D1_PZ3_b D1_U_83 D2_PZ3_b D2_U_83 R1_PZ3_b R2_PZ3_b R2_U_83 R3_U_83 R30_PZ3_b U1_PZ3_b U2_PZ3_b
component class PZ3_c: C1_PZ3_c C1_U_82 C2_PZ3_c C2_U_82 C3_PZ3_c C3_U_82 C4_PZ3_c C5_PZ3_c C5_U_82 D1_PZ3_c D1_U_82 D2_PZ3_c D2_U_82 R1_PZ3_c R2_PZ3_c R2_U_82 R3_U_82 R30_PZ3_c U1_PZ3_c U2_PZ3_c
component class PZ3_d: C1_PZ3_d C1_U_81 C2_PZ3_d C2_U_81 C3_PZ3_d C3_U_81 C4_PZ3_d C5_PZ3_d C5_U_81 D1_PZ3_d D1_U_81 D2_PZ3_d D2_U_81 R1_PZ3_d R2_PZ3_d R2_U_81 R3_U_81 R30_PZ3_d U1_PZ3_d U2_PZ3_d
component class PZ2_b: C1_PZ2_b C1_U_73 C2_PZ2_b C2_U_73 C3_PZ2_b C3_U_73 C4_PZ2_b C5_PZ2_b C5_U_73 D1_PZ2_b D1_U_73 D2_PZ2_b D2_U_73 R1_PZ2_b R2_PZ2_b R2_U_73 R3_U_73 R30_PZ2_b U1_PZ2_b U2_PZ2_b
component class PZ2_c: C1_PZ2_c C1_U_72 C2_PZ2_c C2_U_72 C3_PZ2_c C3_U_72 C4_PZ2_c C5_PZ2_c C5_U_72 D1_PZ2_c D1_U_72 D2_PZ2_c D2_U_72 R1_PZ2_c R2_PZ2_c R2_U_72 R3_U_72 R30_PZ2_c U1_PZ2_c U2_PZ2_c
component class PZ2_d: C1_PZ2_d C1_U_71 C2_PZ2_d C2_U_71 C3_PZ2_d C3_U_71 C4_PZ2_d C5_PZ2_d C5_U_71 D1_PZ2_d D1_U_71 D2_PZ2_d D2_U_71 R1_PZ2_d R2_PZ2_d R2_U_71 R3_U_71 R30_PZ2_d U1_PZ2_d U2_PZ2_d
component class PZ1_b: C1_PZ1_b C1_U_63 C2_PZ1_b C2_U_63 C3_PZ1_b C3_U_63 C4_PZ1_b C5_PZ1_b C5_U_63 D1_PZ1_b D1_U_63 D2_PZ1_b D2_U_63 R1_PZ1_b R2_PZ1_b R2_U_63 R3_U_63 R30_PZ1_b U1_PZ1_b U2_PZ1_b
component class PZ1_c: C1_PZ1_c C1_U_62 C2_PZ1_c C2_U_62 C3_PZ1_c C3_U_62 C4_PZ1_c C5_PZ1_c C5_U_62 D1_PZ1_c D1_U_62 D2_PZ1_c D2_U_62 R1_PZ1_c R2_PZ1_c R2_U_62 R3_U_62 R30_PZ1_c U1_PZ1_c U2_PZ1_c
component class PZ1_d: C1_PZ1_d C1_U_61 C2_PZ1_d C2_U_61 C3_PZ1_d C3_U_61 C4_PZ1_d C5_PZ1_d C5_U_61 D1_PZ1_d D1_U_61 D2_PZ1_d D2_U_61 R1_PZ1_d R2_PZ1_d R2_U_61 R3_U_61 R30_PZ1_d U1_PZ1_d U2_PZ1_d
component class PZ3_a: C1_PZ3_a C2_PZ3_a C3_PZ3_a C4_PZ3_a C5_PZ3_a D1_PZ3_a D2_PZ3_a R1_PZ3_a R2_PZ3_a R3_PZ3_a R30_PZ3_a U1_PZ3_a U2_PZ3_a
component class PZ2_a: C1_PZ2_a C2_PZ2_a C3_PZ2_a C4_PZ2_a C5_PZ2_a D1_PZ2_a D2_PZ2_a R1_PZ2_a R2_PZ2_a R3_PZ2_a R30_PZ2_a U1_PZ2_a U2_PZ2_a
component class PZ1_a: C1_PZ1_a C2_PZ1_a C3_PZ1_a C4_PZ1_a C5_PZ1_a D1_PZ1_a D2_PZ1_a R1_PZ1_a R2_PZ1_a R3_PZ1_a R30_PZ1_a U1_PZ1_a U2_PZ1_a
component class 24dB_d: C24_24dB_d C25_24dB_d C26_24dB_d C27_24dB_d D6_24dB_d D7_24dB_d R11_24dB_d R12_24dB_d R13_24dB_d U8_24dB_d U9_24dB_d
component class 24dB_c: C24_24dB_c C25_24dB_c C26_24dB_c C27_24dB_c D6_24dB_c D7_24dB_c R11_24dB_c R12_24dB_c R13_24dB_c U8_24dB_c U9_24dB_c
component class 24dB_b: C24_24dB_b C25_24dB_b C26_24dB_b C27_24dB_b D6_24dB_b D7_24dB_b R11_24dB_b R12_24dB_b R13_24dB_b U8_24dB_b U9_24dB_b
component class 24dB_a: C24_24dB_a C25_24dB_a C26_24dB_a C27_24dB_a D6_24dB_a D7_24dB_a R11_24dB_a R12_24dB_a R13_24dB_a U8_24dB_a U9_24dB_a
component class 12dB_d: C24_12dB_d C25_12dB_d C26_12dB_d C27_12dB_d D6_12dB_d D7_12dB_d R11_12dB_d R12_12dB_d R13_12dB_d U8_12dB_d U9_12dB_d
component class 12dB_c: C24_12dB_c C25_12dB_c C26_12dB_c C27_12dB_c D6_12dB_c D7_12dB_c R11_12dB_c R12_12dB_c R13_12dB_c U8_12dB_c U9_12dB_c
component class 12dB_b: C24_12dB_b C25_12dB_b C26_12dB_b C27_12dB_b D6_12dB_b D7_12dB_b R11_12dB_b R12_12dB_b R13_12dB_b U8_12dB_b U9_12dB_b
component class 12dB_a: C24_12dB_a C25_12dB_a C26_12dB_a C27_12dB_a D6_12dB_a D7_12dB_a R11_12dB_a R12_12dB_a R13_12dB_a U8_12dB_a U9_12dB_a
component class 6dB_d: C24_6dB_d C25_6dB_d C26_6dB_d C27_6dB_d D6_6dB_d D7_6dB_d R11_6dB_d R12_6dB_d R13_6dB_d U8_6dB_d U9_6dB_d
component class 6dB_c: C24_6dB_c C25_6dB_c C26_6dB_c C27_6dB_c D6_6dB_c D7_6dB_c R11_6dB_c R12_6dB_c R13_6dB_c U8_6dB_c U9_6dB_c
component class 6dB_b: C24_6dB_b C25_6dB_b C26_6dB_b C27_6dB_b D6_6dB_b D7_6dB_b R11_6dB_b R12_6dB_b R13_6dB_b U8_6dB_b U9_6dB_b
component class 6dB_a: C24_6dB_a C25_6dB_a C26_6dB_a C27_6dB_a D6_6dB_a D7_6dB_a R11_6dB_a R12_6dB_a R13_6dB_a U8_6dB_a U9_6dB_a
component class 3dB_d: C24_3dB_d C25_3dB_d C26_3dB_d C27_3dB_d D6_3dB_d D7_3dB_d R11_3dB_d R12_3dB_d R13_3dB_d U8_3dB_d U9_3dB_d
component class 3dB_c: C24_3dB_c C25_3dB_c C26_3dB_c C27_3dB_c D6_3dB_c D7_3dB_c R11_3dB_c R12_3dB_c R13_3dB_c U8_3dB_c U9_3dB_c
component class 3dB_b: C24_3dB_b C25_3dB_b C26_3dB_b C27_3dB_b D6_3dB_b D7_3dB_b R11_3dB_b R12_3dB_b R13_3dB_b U8_3dB_b U9_3dB_b
component class 3dB_a: C24_3dB_a C25_3dB_a C26_3dB_a C27_3dB_a D6_3dB_a D7_3dB_a R11_3dB_a R12_3dB_a R13_3dB_a U8_3dB_a U9_3dB_a
component class U_diff_in_D: C28_U_diff_in_D C29_U_diff_in_D C37_U_diff_in_D C38_U_diff_in_D C39_U_diff_in_D R14_U_diff_in_D R15_U_diff_in_D R16_U_diff_in_D R17_U_diff_in_D R18_U_diff_in_D R19_U_diff_in_D R20_U_diff_in_D R21_U_diff_in_D R22_U_diff_in_D R32_U_diff_in_D R33_U_diff_in_D U9_U_diff_in1 U10_U_diff_in_D
component class U_diff_in_C: C28_U_diff_in_C C29_U_diff_in_C C37_U_diff_in_C C38_U_diff_in_C C39_U_diff_in_C R14_U_diff_in_C R15_U_diff_in_C R16_U_diff_in_C R17_U_diff_in_C R18_U_diff_in_C R19_U_diff_in_C R20_U_diff_in_C R21_U_diff_in_C R22_U_diff_in_C R32_U_diff_in_C R33_U_diff_in_C U9_U_diff_in2 U10_U_diff_in_C
component class U_diff_in_B: C28_U_diff_in_B C29_U_diff_in_B C37_U_diff_in_B C38_U_diff_in_B C39_U_diff_in_B R14_U_diff_in_B R15_U_diff_in_B R16_U_diff_in_B R17_U_diff_in_B R18_U_diff_in_B R19_U_diff_in_B R20_U_diff_in_B R21_U_diff_in_B R22_U_diff_in_B R32_U_diff_in_B R33_U_diff_in_B U9_U_diff_in3 U10_U_diff_in_B
component class U_diff_in_A: C28_U_diff_in_A C29_U_diff_in_A C37_U_diff_in_A C38_U_diff_in_A C39_U_diff_in_A R14_U_diff_in_A R15_U_diff_in_A R16_U_diff_in_A R17_U_diff_in_A R18_U_diff_in_A R19_U_diff_in_A R20_U_diff_in_A R21_U_diff_in_A R22_U_diff_in_A R32_U_diff_in_A R33_U_diff_in_A U9_U_diff_in4 U10_U_diff_in_A
component class U_diff_out_D: C30_U_diff_out_D C31_U_diff_out_D R23_U_diff_out_D R24_U_diff_out_D R25_U_diff_out_D R26_U_diff_out_D R27_U_diff_out_D R28_U_diff_out_D TP7_U_diff_out_D TP8_U_diff_out_D TP9_U_diff_out_D U11_U_diff_out_D
component class U_diff_out_C: C30_U_diff_out_C C31_U_diff_out_C R23_U_diff_out_C R24_U_diff_out_C R25_U_diff_out_C R26_U_diff_out_C R27_U_diff_out_C R28_U_diff_out_C TP7_U_diff_out_C TP8_U_diff_out_C TP9_U_diff_out_C U11_U_diff_out_C
component class U_diff_out_B: C30_U_diff_out_B C31_U_diff_out_B R23_U_diff_out_B R24_U_diff_out_B R25_U_diff_out_B R26_U_diff_out_B R27_U_diff_out_B R28_U_diff_out_B TP7_U_diff_out_B TP8_U_diff_out_B TP9_U_diff_out_B U11_U_diff_out_B
component class U_diff_out_A: C30_U_diff_out_A C31_U_diff_out_A R23_U_diff_out_A R24_U_diff_out_A R25_U_diff_out_A R26_U_diff_out_A R27_U_diff_out_A R28_U_diff_out_A TP7_U_diff_out_A TP8_U_diff_out_A TP9_U_diff_out_A U11_U_diff_out_A
component class dewhite_top: C6 C7 C8 C9 C10 C11 C12 C13 C14 C15 C16 C17 C18 C19 C20 C21 C22 C23 C34 C35 D3 D4 D5 D6 IN1 IN2 IN3 IN4 J5 J6 L1 L2 L5 L6 L7 L8 OUT1 OUT2 OUT3 OUT4 P1 P2 P3 P4 R3 R4 R5 R6 R7 R8 R9 R10 R34 R35 R36 R37 R38 R39 TP1 TP2 TP3 TP4 TP5 TP6 TP9 TP10 TP11 TP12 TP13 TP14 TP15 TP16 TP17 TP18 TP19 TP20 TP21 TP22 U3 U4 U5 U6 U7 U10
net class A[1..7]: A1 A2 A3 A4 A5 A6 A7
net class B[1..7]: B1 B2 B3 B4 B5 B6 B7
net class C[1..7]: C1 C2 C3 C4 C5 C6 C7
net class D[1..7]: D1 D2 D3 D4 D5 D6 D7
channel class diff_out: U_diff_out_A U_diff_out_B U_diff_out_C U_diff_out_D
channel class logic: U_logic_A U_logic_B U_logic_C U_logic_D

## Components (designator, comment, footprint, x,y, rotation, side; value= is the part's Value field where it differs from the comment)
C1_PZ1_a "100n" 3216[1206] 5731,6480 r90 top (schematic designator C1)
C1_PZ1_b "100n" 3216[1206] 5731,5365 r90 top (schematic designator C1)
C1_PZ1_c "100n" 3216[1206] 5731,4250 r90 top (schematic designator C1)
C1_PZ1_d "100n" 3216[1206] 5731,3125 r90 top (schematic designator C1)
C1_PZ2_a "100n" 3216[1206] 6566,6480 r90 top (schematic designator C1)
C1_PZ2_b "100n" 3216[1206] 6566,5365 r90 top (schematic designator C1)
C1_PZ2_c "100n" 3216[1206] 6566,4250 r90 top (schematic designator C1)
C1_PZ2_d "100n" 3216[1206] 6566,3125 r90 top (schematic designator C1)
C1_PZ3_a "100n" 3216[1206] 7401,6480 r90 top (schematic designator C1)
C1_PZ3_b "100n" 3216[1206] 7401,5365 r90 top (schematic designator C1)
C1_PZ3_c "100n" 3216[1206] 7401,4250 r90 top (schematic designator C1)
C1_PZ3_d "100n" 3216[1206] 7401,3125 r90 top (schematic designator C1)
C2_PZ1_a "68p" 3216[1206] 5731,6280 r270 top (schematic designator C2)
C2_PZ1_b "68p" 3216[1206] 5731,5165 r270 top (schematic designator C2)
C2_PZ1_c "68p" 3216[1206] 5731,4050 r270 top (schematic designator C2)
C2_PZ1_d "68p" 3216[1206] 5731,2925 r270 top (schematic designator C2)
C2_PZ2_a "68p" 3216[1206] 6566,6280 r270 top (schematic designator C2)
C2_PZ2_b "68p" 3216[1206] 6566,5165 r270 top (schematic designator C2)
C2_PZ2_c "68p" 3216[1206] 6566,4050 r270 top (schematic designator C2)
C2_PZ2_d "68p" 3216[1206] 6566,2925 r270 top (schematic designator C2)
C2_PZ3_a "68p" 3216[1206] 7401,6280 r270 top (schematic designator C2)
C2_PZ3_b "68p" 3216[1206] 7401,5165 r270 top (schematic designator C2)
C2_PZ3_c "68p" 3216[1206] 7401,4050 r270 top (schematic designator C2)
C2_PZ3_d "68p" 3216[1206] 7401,2925 r270 top (schematic designator C2)
C3_PZ1_a "100n" 3216[1206] 6051,6280 r270 top (schematic designator C3)
C3_PZ1_b "100n" 3216[1206] 6051,5165 r270 top (schematic designator C3)
C3_PZ1_c "100n" 3216[1206] 6051,4050 r270 top (schematic designator C3)
C3_PZ1_d "100n" 3216[1206] 6051,2925 r270 top (schematic designator C3)
C3_PZ2_a "100n" 3216[1206] 6886,6280 r270 top (schematic designator C3)
C3_PZ2_b "100n" 3216[1206] 6886,5165 r270 top (schematic designator C3)
C3_PZ2_c "100n" 3216[1206] 6886,4050 r270 top (schematic designator C3)
C3_PZ2_d "100n" 3216[1206] 6886,2925 r270 top (schematic designator C3)
C3_PZ3_a "100n" 3216[1206] 7721,6280 r270 top (schematic designator C3)
C3_PZ3_b "100n" 3216[1206] 7721,5165 r270 top (schematic designator C3)
C3_PZ3_c "100n" 3216[1206] 7721,4050 r270 top (schematic designator C3)
C3_PZ3_d "100n" 3216[1206] 7721,2925 r270 top (schematic designator C3)
C4_PZ1_a "NL" 3216[1206] 5876,6670 r180 top (schematic designator C4)
C4_PZ1_b "NL" 3216[1206] 5876,5555 r180 top (schematic designator C4)
C4_PZ1_c "NL" 3216[1206] 5876,4440 r180 top (schematic designator C4)
C4_PZ1_d "NL" 3216[1206] 5876,3315 r180 top (schematic designator C4)
C4_PZ2_a "NL" 3216[1206] 6711,6670 r180 top (schematic designator C4)
C4_PZ2_b "NL" 3216[1206] 6711,5555 r180 top (schematic designator C4)
C4_PZ2_c "NL" 3216[1206] 6711,4440 r180 top (schematic designator C4)
C4_PZ2_d "NL" 3216[1206] 6711,3315 r180 top (schematic designator C4)
C4_PZ3_a "NL" 3216[1206] 7546,6670 r180 top (schematic designator C4)
C4_PZ3_b "NL" 3216[1206] 7546,5555 r180 top (schematic designator C4)
C4_PZ3_c "NL" 3216[1206] 7546,4440 r180 top (schematic designator C4)
C4_PZ3_d "NL" 3216[1206] 7546,3315 r180 top (schematic designator C4)
C5_PZ1_a "10UF, Plastic" ECQ-E1106KF_Side 6051,6770 r270 bottom value="10uF, plastic" (schematic designator C5)
C5_PZ1_b "10UF, Plastic" ECQ-E1106KF_Side 6051,5655 r270 bottom value="10uF, plastic" (schematic designator C5)
C5_PZ1_c "10UF, Plastic" ECQ-E1106KF_Side 6051,4540 r270 bottom locked value="10uF, plastic" (schematic designator C5)
C5_PZ1_d "10UF, Plastic" ECQ-E1106KF_Side 6051,3415 r270 bottom locked value="10uF, plastic" (schematic designator C5)
C5_PZ2_a "10UF, Plastic" ECQ-E1106KF_Side 6886,6770 r270 bottom value="10uF, plastic" (schematic designator C5)
C5_PZ2_b "10UF, Plastic" ECQ-E1106KF_Side 6886,5655 r270 bottom value="10uF, plastic" (schematic designator C5)
C5_PZ2_c "10UF, Plastic" ECQ-E1106KF_Side 6890,4540 r270 bottom value="10uF, plastic" (schematic designator C5)
C5_PZ2_d "10UF, Plastic" ECQ-E1106KF_Side 6886,3418 r270 bottom value="10uF, plastic" (schematic designator C5)
C5_PZ3_a "10UF, Plastic" ECQ-E1106KF_Side 7721,6770 r270 bottom value="10uF, plastic" (schematic designator C5)
C5_PZ3_b "10UF, Plastic" ECQ-E1106KF_Side 7721,5655 r270 bottom value="10uF, plastic" (schematic designator C5)
C5_PZ3_c "10UF, Plastic" ECQ-E1106KF_Side 7721,4540 r270 bottom value="10uF, plastic" (schematic designator C5)
C5_PZ3_d "10UF, Plastic" ECQ-E1106KF_Side 7721,3415 r270 bottom value="10uF, plastic" (schematic designator C5)
C6 "100n" 3216[1206] 5680,2035 r180 bottom
C7 "68p" 3216[1206] 5565,1740 r0 top
C8 "100n" 3216[1206] 5665,1845 r0 bottom
C9 "100n" 3216[1206] 6895,2035 r180 bottom
C10 "68p" 3216[1206] 6775,1735 r0 top
C11 "100n" 3216[1206] 6880,1850 r0 bottom
C12 "100n" 3216[1206] 5655,1335 r180 bottom
C13 "68p" 3216[1206] 5545,1040 r0 top
C14 "100n" 3216[1206] 5650,1140 r0 bottom
C15 "100n" 3216[1206] 6905,1315 r180 bottom
C16 "68p" 3216[1206] 6790,1010 r0 top
C17 "100n" 3216[1206] 6895,1125 r0 bottom
C18 "10UF Tantalum, 35V" 7343-31 7035,410 r90 top value=10uF
C19 "100n" 3216[1206] 6895,215 r270 top
C20 "1u" 3216[1206] 5985,115 r180 top
C21 "1u" 3216[1206] 5980,460 r180 top
C22 "100n" 3216[1206] 6765,215 r90 top
C23 "10UF Tantalum, 35V" 7343-31 6615,405 r90 top value=10uF
C24_3dB_a "100n" 3216[1206] 5036,6453 r270 bottom (schematic designator C24)
C24_3dB_b "100n" 3216[1206] 5031,5363 r270 bottom (schematic designator C24)
C24_3dB_c "100n" 3216[1206] 5031,4228 r270 bottom (schematic designator C24)
C24_3dB_d "100n" 3216[1206] 5031,3133 r270 bottom (schematic designator C24)
C24_6dB_a "100n" 3216[1206] 4066,6453 r270 bottom (schematic designator C24)
C24_6dB_b "100n" 3216[1206] 4061,5363 r270 bottom (schematic designator C24)
C24_6dB_c "100n" 3216[1206] 4061,4228 r270 bottom (schematic designator C24)
C24_6dB_d "100n" 3216[1206] 4061,3133 r270 bottom (schematic designator C24)
C24_12dB_a "100n" 3216[1206] 3091,6453 r270 bottom (schematic designator C24)
C24_12dB_b "100n" 3216[1206] 3091,5363 r270 bottom (schematic designator C24)
C24_12dB_c "100n" 3216[1206] 3091,4228 r270 bottom (schematic designator C24)
C24_12dB_d "100n" 3216[1206] 3091,3133 r270 bottom (schematic designator C24)
C24_24dB_a "100n" 3216[1206] 2121,6453 r270 bottom (schematic designator C24)
C24_24dB_b "100n" 3216[1206] 2121,5363 r270 bottom (schematic designator C24)
C24_24dB_c "100n" 3216[1206] 2121,4228 r270 bottom (schematic designator C24)
C24_24dB_d "100n" 3216[1206] 2121,3133 r270 bottom (schematic designator C24)
C25_3dB_a "68p" 3216[1206] 5391,6403 r180 top (schematic designator C25)
C25_3dB_b "68p" 3216[1206] 5386,5313 r180 top (schematic designator C25)
C25_3dB_c "68p" 3216[1206] 5386,4178 r180 top (schematic designator C25)
C25_3dB_d "68p" 3216[1206] 5386,3083 r180 top (schematic designator C25)
C25_6dB_a "68p" 3216[1206] 4421,6403 r180 top (schematic designator C25)
C25_6dB_b "68p" 3216[1206] 4416,5313 r180 top (schematic designator C25)
C25_6dB_c "68p" 3216[1206] 4416,4178 r180 top (schematic designator C25)
C25_6dB_d "68p" 3216[1206] 4416,3083 r180 top (schematic designator C25)
C25_12dB_a "68p" 3216[1206] 3446,6403 r180 top (schematic designator C25)
C25_12dB_b "68p" 3216[1206] 3446,5313 r180 top (schematic designator C25)
C25_12dB_c "68p" 3216[1206] 3446,4178 r180 top (schematic designator C25)
C25_12dB_d "68p" 3216[1206] 3446,3083 r180 top (schematic designator C25)
C25_24dB_a "68p" 3216[1206] 2476,6403 r180 top (schematic designator C25)
C25_24dB_b "68p" 3216[1206] 2476,5313 r180 top (schematic designator C25)
C25_24dB_c "68p" 3216[1206] 2476,4178 r180 top (schematic designator C25)
C25_24dB_d "68p" 3216[1206] 2476,3083 r180 top (schematic designator C25)
C26_3dB_a "100n" 3216[1206] 5171,6638 r0 bottom (schematic designator C26)
C26_3dB_b "100n" 3216[1206] 5166,5548 r0 bottom (schematic designator C26)
C26_3dB_c "100n" 3216[1206] 5166,4413 r0 bottom (schematic designator C26)
C26_3dB_d "100n" 3216[1206] 5166,3318 r0 bottom (schematic designator C26)
C26_6dB_a "100n" 3216[1206] 4201,6638 r0 bottom (schematic designator C26)
C26_6dB_b "100n" 3216[1206] 4196,5548 r0 bottom (schematic designator C26)
C26_6dB_c "100n" 3216[1206] 4196,4413 r0 bottom (schematic designator C26)
C26_6dB_d "100n" 3216[1206] 4196,3318 r0 bottom (schematic designator C26)
C26_12dB_a "100n" 3216[1206] 3226,6638 r0 bottom (schematic designator C26)
C26_12dB_b "100n" 3216[1206] 3226,5548 r0 bottom (schematic designator C26)
C26_12dB_c "100n" 3216[1206] 3226,4413 r0 bottom (schematic designator C26)
C26_12dB_d "100n" 3216[1206] 3226,3318 r0 bottom (schematic designator C26)
C26_24dB_a "100n" 3216[1206] 2256,6638 r0 bottom (schematic designator C26)
C26_24dB_b "100n" 3216[1206] 2256,5548 r0 bottom (schematic designator C26)
C26_24dB_c "100n" 3216[1206] 2256,4413 r0 bottom (schematic designator C26)
C26_24dB_d "100n" 3216[1206] 2256,3318 r0 bottom (schematic designator C26)
C27_3dB_a "NL" 3216[1206] 4866,6573 r0 top (schematic designator C27)
C27_3dB_b "NL" 3216[1206] 4861,5483 r0 top (schematic designator C27)
C27_3dB_c "NL" 3216[1206] 4861,4348 r0 top (schematic designator C27)
C27_3dB_d "NL" 3216[1206] 4861,3253 r0 top (schematic designator C27)
C27_6dB_a "NL" 3216[1206] 3896,6573 r0 top (schematic designator C27)
C27_6dB_b "NL" 3216[1206] 3891,5483 r0 top (schematic designator C27)
C27_6dB_c "NL" 3216[1206] 3891,4348 r0 top (schematic designator C27)
C27_6dB_d "NL" 3216[1206] 3891,3253 r0 top (schematic designator C27)
C27_12dB_a "NL" 3216[1206] 2921,6573 r0 top (schematic designator C27)
C27_12dB_b "NL" 3216[1206] 2921,5483 r0 top (schematic designator C27)
C27_12dB_c "NL" 3216[1206] 2921,4348 r0 top (schematic designator C27)
C27_12dB_d "NL" 3216[1206] 2921,3253 r0 top (schematic designator C27)
C27_24dB_a "NL" 3216[1206] 1951,6573 r0 top (schematic designator C27)
C27_24dB_b "NL" 3216[1206] 1951,5483 r0 top (schematic designator C27)
C27_24dB_c "NL" 3216[1206] 1951,4348 r0 top (schematic designator C27)
C27_24dB_d "NL" 3216[1206] 1951,3253 r0 top (schematic designator C27)
C28_U_diff_in_A "1u" 3216[1206] 974.53,6491.5 r270 bottom (schematic designator C28)
C28_U_diff_in_B "1u" 3216[1206] 974.53,5511.5 r270 bottom (schematic designator C28)
C28_U_diff_in_C "1u" 3216[1206] 974.53,4386.5 r270 bottom (schematic designator C28)
C28_U_diff_in_D "1u" 3216[1206] 974.53,3266.5 r270 bottom (schematic designator C28)
C29_U_diff_in_A "1u" 3216[1206] 1330,6600 r90 bottom (schematic designator C29)
C29_U_diff_in_B "1u" 3216[1206] 1330,5620 r90 bottom (schematic designator C29)
C29_U_diff_in_C "1u" 3216[1206] 1330,4495 r90 bottom (schematic designator C29)
C29_U_diff_in_D "1u" 3216[1206] 1325,3375 r90 bottom (schematic designator C29)
C30_U_diff_out_A "100n" 3216[1206] 6140,1840 r180 bottom (schematic designator C30)
C30_U_diff_out_B "100n" 3216[1206] 7375,1840 r180 bottom (schematic designator C30)
C30_U_diff_out_C "100n" 3216[1206] 6135,1125 r180 bottom (schematic designator C30)
C30_U_diff_out_D "100n" 3216[1206] 7375,1125 r180 bottom (schematic designator C30)
C31_U_diff_out_A "100n" 3216[1206] 6100,2030 r0 bottom (schematic designator C31)
C31_U_diff_out_B "100n" 3216[1206] 7335,2030 r0 bottom (schematic designator C31)
C31_U_diff_out_C "100n" 3216[1206] 6095,1315 r0 bottom (schematic designator C31)
C31_U_diff_out_D "100n" 3216[1206] 7335,1315 r0 bottom (schematic designator C31)
C32_U_logic_A "100n" 3216[1206] 3510,6070 r0 bottom (schematic designator C32)
C32_U_logic_B "100n" 3216[1206] 3515,4997.36 r0 bottom (schematic designator C32)
C32_U_logic_C "100n" 3216[1206] 3510,3865 r0 bottom (schematic designator C32)
C32_U_logic_D "100n" 3216[1206] 3510,2725 r0 bottom (schematic designator C32)
C33_U_logic_A "100n" 3216[1206] 2745,6097 r90 bottom (schematic designator C33)
C33_U_logic_B "100n" 3216[1206] 2750,5025 r90 bottom (schematic designator C33)
C33_U_logic_C "100n" 3216[1206] 2750,3895 r90 bottom (schematic designator C33)
C33_U_logic_D "100n" 3216[1206] 2750,2775 r90 bottom (schematic designator C33)
C34 "1u" 3216[1206] 165,6440 r270 bottom
C35 "1u" 3216[1206] 8065,1230 r90 bottom
C36_U_logic_A "100n" 3216[1206] 3995,6080 r0 bottom (schematic designator C36)
C36_U_logic_B "100n" 3216[1206] 4005,4997.36 r0 bottom (schematic designator C36)
C36_U_logic_C "100n" 3216[1206] 4005,3865 r0 bottom (schematic designator C36)
C36_U_logic_D "100n" 3216[1206] 4005,2745 r0 bottom (schematic designator C36)
C37_U_diff_in_A "5.6n" 3216[1206] 1510,6735 r180 top (schematic designator C37)
C37_U_diff_in_B "5.6n" 3216[1206] 1510,5755 r180 top (schematic designator C37)
C37_U_diff_in_C "5.6n" 3216[1206] 1510,4630 r180 top (schematic designator C37)
C37_U_diff_in_D "5.6n" 3216[1206] 1510,3510 r180 top (schematic designator C37)
C38_U_diff_in_A "5.6n" 3216[1206] 860,6540 r270 top (schematic designator C38)
C38_U_diff_in_B "5.6n" 3216[1206] 860,5560 r270 top (schematic designator C38)
C38_U_diff_in_C "5.6n" 3216[1206] 860,4435 r270 top (schematic designator C38)
C38_U_diff_in_D "5.6n" 3216[1206] 860,3315 r270 top (schematic designator C38)
C39_U_diff_in_A "5.6n" 3216[1206] 1515,6250 r0 top (schematic designator C39)
C39_U_diff_in_B "5.6n" 3216[1206] 1515,5270 r0 top (schematic designator C39)
C39_U_diff_in_C "5.6n" 3216[1206] 1515,4145 r0 top (schematic designator C39)
C39_U_diff_in_D "5.6n" 3216[1206] 1515,3025 r0 top (schematic designator C39)
D1_PZ1_a "60V, 1A Schottky" sod123 5670,5950 r270 top value="Diode 1 Amp" (schematic designator D1)
D1_PZ1_b "60V, 1A Schottky" sod123 5670,4835 r270 top value="Diode 1 Amp" (schematic designator D1)
D1_PZ1_c "60V, 1A Schottky" sod123 5670,3720 r270 top value="Diode 1 Amp" (schematic designator D1)
D1_PZ1_d "60V, 1A Schottky" sod123 5670,2595 r270 top value="Diode 1 Amp" (schematic designator D1)
D1_PZ2_a "60V, 1A Schottky" sod123 6505,5950 r270 top value="Diode 1 Amp" (schematic designator D1)
D1_PZ2_b "60V, 1A Schottky" sod123 6505,4835 r270 top value="Diode 1 Amp" (schematic designator D1)
D1_PZ2_c "60V, 1A Schottky" sod123 6505,3720 r270 top value="Diode 1 Amp" (schematic designator D1)
D1_PZ2_d "60V, 1A Schottky" sod123 6505,2595 r270 top value="Diode 1 Amp" (schematic designator D1)
D1_PZ3_a "60V, 1A Schottky" sod123 7340,5950 r270 top value="Diode 1 Amp" (schematic designator D1)
D1_PZ3_b "60V, 1A Schottky" sod123 7340,4835 r270 top value="Diode 1 Amp" (schematic designator D1)
D1_PZ3_c "60V, 1A Schottky" sod123 7340,3720 r270 top value="Diode 1 Amp" (schematic designator D1)
D1_PZ3_d "60V, 1A Schottky" sod123 7340,2595 r270 top value="Diode 1 Amp" (schematic designator D1)
D2_PZ1_a "60V, 1A Schottky" sod123 6110,6005 r90 top value="Diode 1 Amp" (schematic designator D2)
D2_PZ1_b "60V, 1A Schottky" sod123 6110,4890 r90 top value="Diode 1 Amp" (schematic designator D2)
D2_PZ1_c "60V, 1A Schottky" sod123 6110,3775 r90 top value="Diode 1 Amp" (schematic designator D2)
D2_PZ1_d "60V, 1A Schottky" sod123 6110,2650 r90 top value="Diode 1 Amp" (schematic designator D2)
D2_PZ2_a "60V, 1A Schottky" sod123 6945,6005 r90 top value="Diode 1 Amp" (schematic designator D2)
D2_PZ2_b "60V, 1A Schottky" sod123 6945,4890 r90 top value="Diode 1 Amp" (schematic designator D2)
D2_PZ2_c "60V, 1A Schottky" sod123 6945,3775 r90 top value="Diode 1 Amp" (schematic designator D2)
D2_PZ2_d "60V, 1A Schottky" sod123 6945,2650 r90 top value="Diode 1 Amp" (schematic designator D2)
D2_PZ3_a "60V, 1A Schottky" sod123 7780,6005 r90 top value="Diode 1 Amp" (schematic designator D2)
D2_PZ3_b "60V, 1A Schottky" sod123 7780,4890 r90 top value="Diode 1 Amp" (schematic designator D2)
D2_PZ3_c "60V, 1A Schottky" sod123 7780,3775 r90 top value="Diode 1 Amp" (schematic designator D2)
D2_PZ3_d "60V, 1A Schottky" sod123 7780,2650 r90 top value="Diode 1 Amp" (schematic designator D2)
D3 "60V, 1A Schottky" sod123 5990,355 r0 top value="Diode 1 Amp"
D4 "Stacked LED" "my LUMEX Dual LED" 255,3830 r0 top locked
D5 "60V, 1A Schottky" sod123 5990,225 r0 top value="Diode 1 Amp"
D6_3dB_a "60V, 1A Schottky" sod123 5191,6393 r180 bottom value="Diode 1 Amp" (schematic designator D6)
D6_3dB_b "60V, 1A Schottky" sod123 5186,5303 r180 bottom value="Diode 1 Amp" (schematic designator D6)
D6_3dB_c "60V, 1A Schottky" sod123 5186,4168 r180 bottom value="Diode 1 Amp" (schematic designator D6)
D6_3dB_d "60V, 1A Schottky" sod123 5186,3073 r180 bottom value="Diode 1 Amp" (schematic designator D6)
D6_6dB_a "60V, 1A Schottky" sod123 4221,6393 r180 bottom value="Diode 1 Amp" (schematic designator D6)
D6_6dB_b "60V, 1A Schottky" sod123 4216,5303 r180 bottom value="Diode 1 Amp" (schematic designator D6)
D6_6dB_c "60V, 1A Schottky" sod123 4216,4168 r180 bottom value="Diode 1 Amp" (schematic designator D6)
D6_6dB_d "60V, 1A Schottky" sod123 4216,3073 r180 bottom value="Diode 1 Amp" (schematic designator D6)
D6_12dB_a "60V, 1A Schottky" sod123 3246,6393 r180 bottom value="Diode 1 Amp" (schematic designator D6)
D6_12dB_b "60V, 1A Schottky" sod123 3246,5303 r180 bottom value="Diode 1 Amp" (schematic designator D6)
D6_12dB_c "60V, 1A Schottky" sod123 3246,4168 r180 bottom value="Diode 1 Amp" (schematic designator D6)
D6_12dB_d "60V, 1A Schottky" sod123 3246,3073 r180 bottom value="Diode 1 Amp" (schematic designator D6)
D6_24dB_a "60V, 1A Schottky" sod123 2276,6393 r180 bottom value="Diode 1 Amp" (schematic designator D6)
D6_24dB_b "60V, 1A Schottky" sod123 2276,5303 r180 bottom value="Diode 1 Amp" (schematic designator D6)
D6_24dB_c "60V, 1A Schottky" sod123 2276,4168 r180 bottom value="Diode 1 Amp" (schematic designator D6)
D6_24dB_d "60V, 1A Schottky" sod123 2276,3073 r180 bottom value="Diode 1 Amp" (schematic designator D6)
D7_3dB_a "60V, 1A Schottky" sod123 5191,6528 r180 bottom value="Diode 1 Amp" (schematic designator D7)
D7_3dB_b "60V, 1A Schottky" sod123 5186,5438 r180 bottom value="Diode 1 Amp" (schematic designator D7)
D7_3dB_c "60V, 1A Schottky" sod123 5186,4303 r180 bottom value="Diode 1 Amp" (schematic designator D7)
D7_3dB_d "60V, 1A Schottky" sod123 5186,3208 r180 bottom value="Diode 1 Amp" (schematic designator D7)
D7_6dB_a "60V, 1A Schottky" sod123 4221,6528 r180 bottom value="Diode 1 Amp" (schematic designator D7)
D7_6dB_b "60V, 1A Schottky" sod123 4216,5438 r180 bottom value="Diode 1 Amp" (schematic designator D7)
D7_6dB_c "60V, 1A Schottky" sod123 4216,4303 r180 bottom value="Diode 1 Amp" (schematic designator D7)
D7_6dB_d "60V, 1A Schottky" sod123 4216,3208 r180 bottom value="Diode 1 Amp" (schematic designator D7)
D7_12dB_a "60V, 1A Schottky" sod123 3246,6528 r180 bottom value="Diode 1 Amp" (schematic designator D7)
D7_12dB_b "60V, 1A Schottky" sod123 3246,5438 r180 bottom value="Diode 1 Amp" (schematic designator D7)
D7_12dB_c "60V, 1A Schottky" sod123 3246,4303 r180 bottom value="Diode 1 Amp" (schematic designator D7)
D7_12dB_d "60V, 1A Schottky" sod123 3246,3208 r180 bottom value="Diode 1 Amp" (schematic designator D7)
D7_24dB_a "60V, 1A Schottky" sod123 2276,6528 r180 bottom value="Diode 1 Amp" (schematic designator D7)
D7_24dB_b "60V, 1A Schottky" sod123 2276,5438 r180 bottom value="Diode 1 Amp" (schematic designator D7)
D7_24dB_c "60V, 1A Schottky" sod123 2276,4303 r180 bottom value="Diode 1 Amp" (schematic designator D7)
D7_24dB_d "60V, 1A Schottky" sod123 2276,3208 r180 bottom value="Diode 1 Amp" (schematic designator D7)
IN1 "SMA" SMA 900,4950 r270 top
IN2 "SMA" SMA 1350,4950 r270 top
IN3 "SMA" SMA 900,3825 r270 top
IN4 "SMA" SMA 1350,3825 r270 top
J5 "D Connector 15" DSUB1.385-2H15 0,5470 r90 top locked value="15 pin connector Receptacle"
J6 "D Connector 9" DSUB1.385-2H9 8440,2070 r270 top value="9 pin connector Receptacle"
L1 "NL" 1812 7345,585 r180 top
L2 "NL" 1812 7345,190 r180 top
L5 "10UH, 360mA" 1812 130,3115 r90 bottom value="10uH, 360mA"
L6 "10UH, 360mA" 1812 320,3115 r90 bottom value="10uH, 360mA"
L7 "10UH, 360mA" 1812 8310,3330 r270 bottom value="10uH, 360mA"
L8 "10UH, 360mA" 1812 8115,3330 r270 bottom value="10uH, 360mA"
OUT1 "SMA" SMA 4650,2000 r90 top
OUT2 "SMA" SMA 5200,2000 r90 top
OUT3 "SMA" SMA 4650,1300 r90 top
OUT4 "SMA" SMA 5200,1300 r90 top
P1 "37 pin connector" DB37/F/RA/125MT 430,620 r90 top locked value="37 pin connector Receptacle"
P2 "Header 20X2H" MY_40-pin_Header_RA 920,410 r90 bottom
P3 "37 pin connector" DB37/F/RA/125MT 8040,5840 r270 top value="37 pin connector Receptacle"
P4 "Header 3H" Molex_156_RA_3 7640,785 r0 top
R1_PZ1_a "0" 3216[1206] 5876,6580 r0 top (schematic designator R1)
R1_PZ1_b "0" 3216[1206] 5876,5465 r0 top (schematic designator R1)
R1_PZ1_c "0" 3216[1206] 5876,4350 r0 top (schematic designator R1)
R1_PZ1_d "0" 3216[1206] 5876,3225 r0 top (schematic designator R1)
R1_PZ2_a "0" 3216[1206] 6711,6580 r0 top (schematic designator R1)
R1_PZ2_b "0" 3216[1206] 6711,5465 r0 top (schematic designator R1)
R1_PZ2_c "0" 3216[1206] 6711,4350 r0 top (schematic designator R1)
R1_PZ2_d "0" 3216[1206] 6711,3225 r0 top (schematic designator R1)
R1_PZ3_a "0" 3216[1206] 7546,6580 r0 top (schematic designator R1)
R1_PZ3_b "0" 3216[1206] 7546,5465 r0 top (schematic designator R1)
R1_PZ3_c "0" 3216[1206] 7546,4350 r0 top (schematic designator R1)
R1_PZ3_d "0" 3216[1206] 7546,3225 r0 top (schematic designator R1)
R2_PZ1_a "1.58k" 3216[1206] 5901,6770 r180 top (schematic designator R2)
R2_PZ1_b "1.58k" 3216[1206] 5901,5655 r180 top (schematic designator R2)
R2_PZ1_c "1.58k" 3216[1206] 5901,4540 r180 top (schematic designator R2)
R2_PZ1_d "1.58k" 3216[1206] 5901,3415 r180 top (schematic designator R2)
R2_PZ2_a "1.58k" 3216[1206] 6736,6770 r180 top (schematic designator R2)
R2_PZ2_b "1.58k" 3216[1206] 6736,5655 r180 top (schematic designator R2)
R2_PZ2_c "1.58k" 3216[1206] 6736,4540 r180 top (schematic designator R2)
R2_PZ2_d "1.58k" 3216[1206] 6736,3415 r180 top (schematic designator R2)
R2_PZ3_a "1.58k" 3216[1206] 7571,6770 r180 top (schematic designator R2)
R2_PZ3_b "1.58k" 3216[1206] 7571,5655 r180 top (schematic designator R2)
R2_PZ3_c "1.58k" 3216[1206] 7571,4540 r180 top (schematic designator R2)
R2_PZ3_d "1.58k" 3216[1206] 7571,3415 r180 top (schematic designator R2)
R3 "0" 3216[1206] 5760,2150 r0 top
R4 "0" 3216[1206] 6985,2170 r0 top
R5 "0" 3216[1206] 5755,1450 r0 top
R6 "0" 3216[1206] 6990,1440 r0 top
R7 "1K" 3216[1206] 305,6440 r90 top
R8 "1K" 3216[1206] 165,6440 r90 top
R9 "1K" 3216[1206] 205,3625 r0 top
R10 "1K" 3216[1206] 200,3925 r180 top
R11_3dB_a "680" 3216[1206] 5170,6635 r180 top (schematic designator R11)
R11_3dB_b "680" 3216[1206] 5165,5545 r180 top (schematic designator R11)
R11_3dB_c "680" 3216[1206] 5165,4410 r180 top (schematic designator R11)
R11_3dB_d "680" 3216[1206] 5165,3315 r180 top (schematic designator R11)
R11_6dB_a "1K" 3216[1206] 4200,6635 r180 top (schematic designator R11)
R11_6dB_b "1K" 3216[1206] 4195,5545 r180 top (schematic designator R11)
R11_6dB_c "1K" 3216[1206] 4195,4410 r180 top (schematic designator R11)
R11_6dB_d "1K" 3216[1206] 4195,3315 r180 top (schematic designator R11)
R11_12dB_a "1.65K" 3216[1206] 3225,6635 r180 top (schematic designator R11)
R11_12dB_b "1.65K" 3216[1206] 3225,5545 r180 top (schematic designator R11)
R11_12dB_c "1.65K" 3216[1206] 3225,4410 r180 top (schematic designator R11)
R11_12dB_d "1.65K" 3216[1206] 3225,3315 r180 top (schematic designator R11)
R11_24dB_a "3K" 3216[1206] 2255,6635 r180 top (schematic designator R11)
R11_24dB_b "3K" 3216[1206] 2255,5545 r180 top (schematic designator R11)
R11_24dB_c "3K" 3216[1206] 2255,4410 r180 top (schematic designator R11)
R11_24dB_d "3K" 3216[1206] 2255,3315 r180 top (schematic designator R11)
R12_3dB_a "1.65K" 3216[1206] 4866,6393 r0 top (schematic designator R12)
R12_3dB_b "1.65K" 3216[1206] 4861,5303 r0 top (schematic designator R12)
R12_3dB_c "1.65K" 3216[1206] 4861,4168 r0 top (schematic designator R12)
R12_3dB_d "1.65K" 3216[1206] 4861,3073 r0 top (schematic designator R12)
R12_6dB_a "1K" 3216[1206] 3896,6393 r0 top (schematic designator R12)
R12_6dB_b "1K" 3216[1206] 3891,5303 r0 top (schematic designator R12)
R12_6dB_c "1K" 3216[1206] 3891,4168 r0 top (schematic designator R12)
R12_6dB_d "1K" 3216[1206] 3891,3073 r0 top (schematic designator R12)
R12_12dB_a "549" 3216[1206] 2921,6393 r0 top (schematic designator R12)
R12_12dB_b "549" 3216[1206] 2921,5303 r0 top (schematic designator R12)
R12_12dB_c "549" 3216[1206] 2921,4168 r0 top (schematic designator R12)
R12_12dB_d "549" 3216[1206] 2921,3073 r0 top (schematic designator R12)
R12_24dB_a "200" 3216[1206] 1951,6393 r0 top (schematic designator R12)
R12_24dB_b "200" 3216[1206] 1951,5303 r0 top (schematic designator R12)
R12_24dB_c "200" 3216[1206] 1951,4168 r0 top (schematic designator R12)
R12_24dB_d "200" 3216[1206] 1951,3073 r0 top (schematic designator R12)
R13_3dB_a "0" 3216[1206] 4866,6483 r180 top (schematic designator R13)
R13_3dB_b "0" 3216[1206] 4861,5393 r180 top (schematic designator R13)
R13_3dB_c "0" 3216[1206] 4861,4258 r180 top (schematic designator R13)
R13_3dB_d "0" 3216[1206] 4861,3163 r180 top (schematic designator R13)
R13_6dB_a "0" 3216[1206] 3896,6483 r180 top (schematic designator R13)
R13_6dB_b "0" 3216[1206] 3891,5393 r180 top (schematic designator R13)
R13_6dB_c "0" 3216[1206] 3891,4258 r180 top (schematic designator R13)
R13_6dB_d "0" 3216[1206] 3891,3163 r180 top (schematic designator R13)
R13_12dB_a "0" 3216[1206] 2921,6483 r180 top (schematic designator R13)
R13_12dB_b "0" 3216[1206] 2921,5393 r180 top (schematic designator R13)
R13_12dB_c "0" 3216[1206] 2921,4258 r180 top (schematic designator R13)
R13_12dB_d "0" 3216[1206] 2921,3163 r180 top (schematic designator R13)
R13_24dB_a "0" 3216[1206] 1951,6483 r180 top (schematic designator R13)
R13_24dB_b "0" 3216[1206] 1951,5393 r180 top (schematic designator R13)
R13_24dB_c "0" 3216[1206] 1951,4258 r180 top (schematic designator R13)
R13_24dB_d "0" 3216[1206] 1951,3163 r180 top (schematic designator R13)
R14_U_diff_in_A "1M" 3216[1206] 755,6235 r180 bottom (schematic designator R14)
R14_U_diff_in_B "1M" 3216[1206] 755,5255 r180 bottom (schematic designator R14)
R14_U_diff_in_C "1M" 3216[1206] 755,4130 r180 bottom (schematic designator R14)
R14_U_diff_in_D "1M" 3216[1206] 810,3060 r180 bottom (schematic designator R14)
R15_U_diff_in_A "3K" 3216[1206] 1510,6535 r0 top (schematic designator R15)
R15_U_diff_in_B "3K" 3216[1206] 1510,5555 r0 top (schematic designator R15)
R15_U_diff_in_C "3K" 3216[1206] 1510,4430 r0 top (schematic designator R15)
R15_U_diff_in_D "3K" 3216[1206] 1510,3310 r0 top (schematic designator R15)
R16_U_diff_in_A "3K" 3216[1206] 1510,6635 r0 top (schematic designator R16)
R16_U_diff_in_B "3K" 3216[1206] 1510,5655 r0 top (schematic designator R16)
R16_U_diff_in_C "3K" 3216[1206] 1510,4530 r0 top (schematic designator R16)
R16_U_diff_in_D "3K" 3216[1206] 1510,3410 r0 top (schematic designator R16)
R17_U_diff_in_A "0" 3216[1206] 810,6300 r180 top (schematic designator R17)
R17_U_diff_in_B "0" 3216[1206] 810,5320 r180 top (schematic designator R17)
R17_U_diff_in_C "0" 3216[1206] 810,4195 r180 top (schematic designator R17)
R17_U_diff_in_D "0" 3216[1206] 810,3075 r180 top (schematic designator R17)
R18_U_diff_in_A "NL" 3216[1206] 760,6540 r270 top (schematic designator R18)
R18_U_diff_in_B "NL" 3216[1206] 760,5560 r270 top (schematic designator R18)
R18_U_diff_in_C "NL" 3216[1206] 760,4435 r270 top (schematic designator R18)
R18_U_diff_in_D "NL" 3216[1206] 760,3315 r270 top (schematic designator R18)
R19_U_diff_in_A "0" 3216[1206] 810,6780 r180 top (schematic designator R19)
R19_U_diff_in_B "0" 3216[1206] 810,5800 r180 top (schematic designator R19)
R19_U_diff_in_C "0" 3216[1206] 810,4675 r180 top (schematic designator R19)
R19_U_diff_in_D "0" 3216[1206] 810,3555 r180 top (schematic designator R19)
R20_U_diff_in_A "3K" 3216[1206] 1515,6345 r180 top (schematic designator R20)
R20_U_diff_in_B "3K" 3216[1206] 1515,5365 r180 top (schematic designator R20)
R20_U_diff_in_C "3K" 3216[1206] 1515,4240 r180 top (schematic designator R20)
R20_U_diff_in_D "3K" 3216[1206] 1515,3120 r180 top (schematic designator R20)
R21_U_diff_in_A "3K" 3216[1206] 1510,6440 r0 top (schematic designator R21)
R21_U_diff_in_B "3K" 3216[1206] 1510,5460 r0 top (schematic designator R21)
R21_U_diff_in_C "3K" 3216[1206] 1510,4335 r0 top (schematic designator R21)
R21_U_diff_in_D "3K" 3216[1206] 1510,3215 r0 top (schematic designator R21)
R22_U_diff_in_A "1M" 3216[1206] 750,6755 r0 bottom (schematic designator R22)
R22_U_diff_in_B "1M" 3216[1206] 750,5775 r0 bottom (schematic designator R22)
R22_U_diff_in_C "1M" 3216[1206] 750,4650 r0 bottom (schematic designator R22)
R22_U_diff_in_D "1M" 3216[1206] 750,3530 r0 bottom (schematic designator R22)
R23_U_diff_out_A "0" 3216[1206] 6330,2035 r0 top (schematic designator R23)
R23_U_diff_out_B "0" 3216[1206] 7565,2035 r0 top (schematic designator R23)
R23_U_diff_out_C "0" 3216[1206] 6325,1320 r0 top (schematic designator R23)
R23_U_diff_out_D "0" 3216[1206] 7565,1320 r0 top (schematic designator R23)
R24_U_diff_out_A "4.99K" 3216[1206] 5960,1990 r90 top (schematic designator R24)
R24_U_diff_out_B "4.99K" 3216[1206] 7195,1990 r90 top (schematic designator R24)
R24_U_diff_out_C "4.99K" 3216[1206] 5955,1275 r90 top (schematic designator R24)
R24_U_diff_out_D "4.99K" 3216[1206] 7195,1275 r90 top (schematic designator R24)
R25_U_diff_out_A "4.99K" 3216[1206] 6200,2130 r0 top (schematic designator R25)
R25_U_diff_out_B "4.99K" 3216[1206] 7435,2130 r0 top (schematic designator R25)
R25_U_diff_out_C "4.99K" 3216[1206] 6195,1415 r0 top (schematic designator R25)
R25_U_diff_out_D "4.99K" 3216[1206] 7435,1415 r0 top (schematic designator R25)
R26_U_diff_out_A "0" 3216[1206] 6335,1845 r0 top (schematic designator R26)
R26_U_diff_out_B "0" 3216[1206] 7570,1845 r0 top (schematic designator R26)
R26_U_diff_out_C "0" 3216[1206] 6330,1130 r0 top (schematic designator R26)
R26_U_diff_out_D "0" 3216[1206] 7570,1130 r0 top (schematic designator R26)
R27_U_diff_out_A "4.99K" 3216[1206] 5925,1790 r270 top (schematic designator R27)
R27_U_diff_out_B "4.99K" 3216[1206] 7160,1790 r270 top (schematic designator R27)
R27_U_diff_out_C "4.99K" 3216[1206] 5920,1075 r270 top (schematic designator R27)
R27_U_diff_out_D "4.99K" 3216[1206] 7160,1075 r270 top (schematic designator R27)
R28_U_diff_out_A "4.99K" 3216[1206] 6115,1735 r0 top (schematic designator R28)
R28_U_diff_out_B "4.99K" 3216[1206] 7350,1735 r0 top (schematic designator R28)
